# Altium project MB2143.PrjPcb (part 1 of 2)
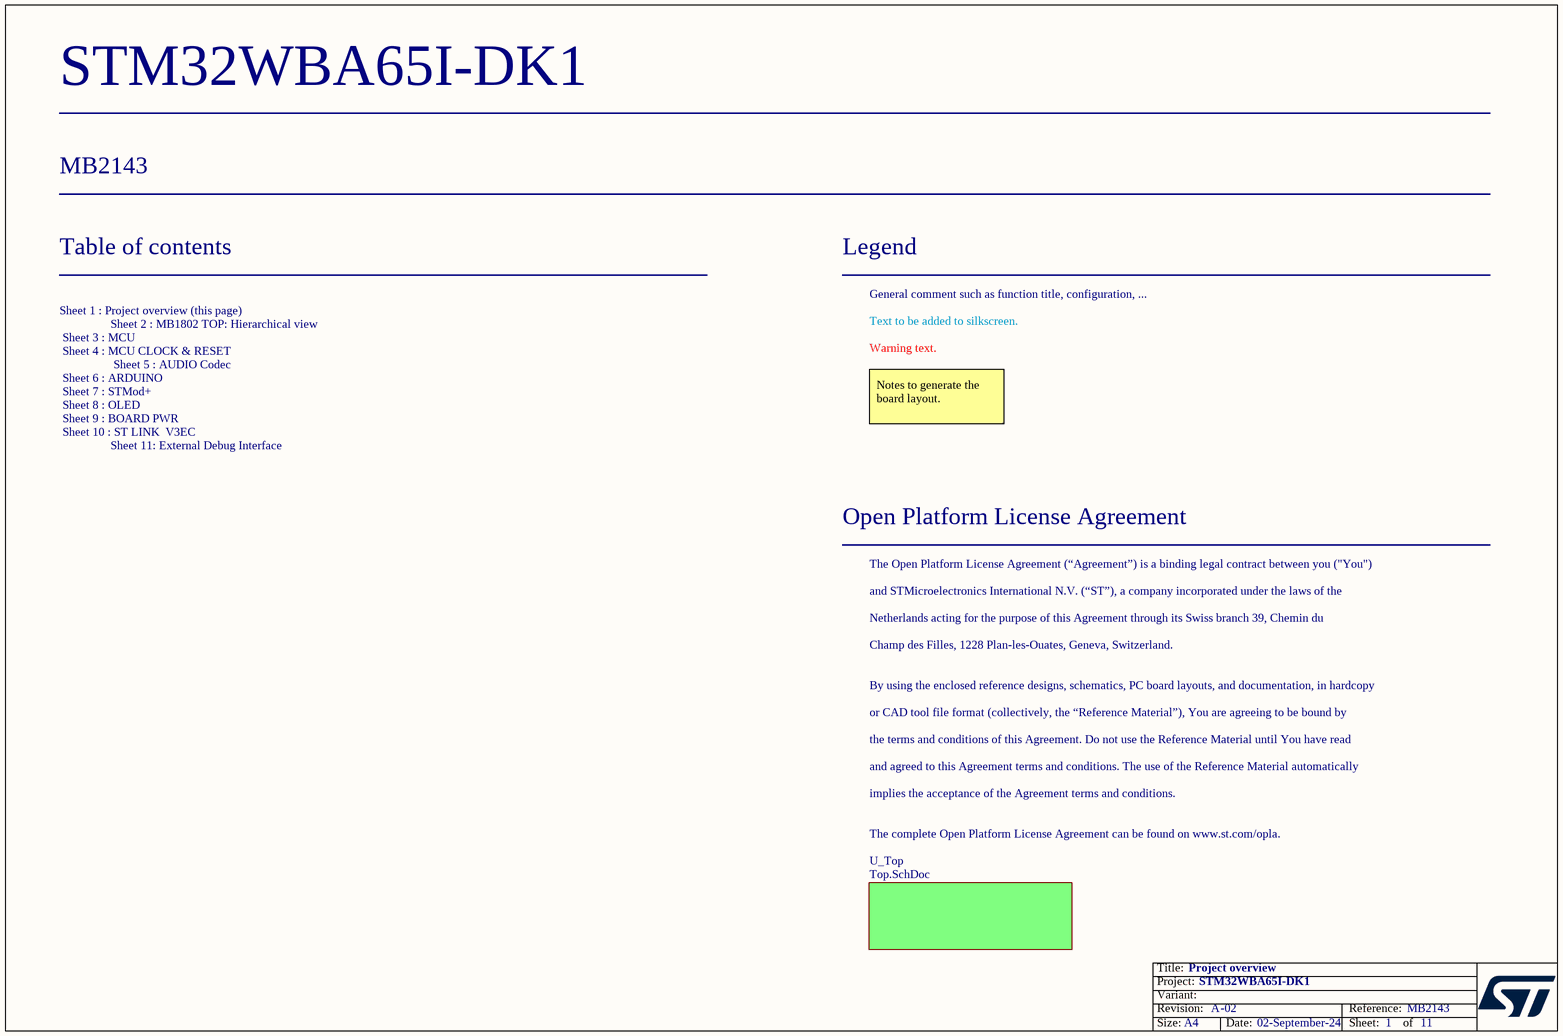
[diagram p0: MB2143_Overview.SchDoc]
Board_Assembly_Revision: 02; Board_Document_Date: 02-September-24; Board_Name: STM32WBA65I-DK1; Board_PCB_Revision: A; Board_Reference: MB2143
10 sheets, 267 parts. Net scope: flat (ports and power ports of the same name join across sheets).
Board file: MB2143.PcbDoc
Sheets:
  MB2143_Overview.SchDoc
    U_Top = Top.SchDoc
      U_Board_Power = Board_Power.SchDoc
      U_External_Debug_Interface = External_Debug_Interface.SchDoc
      U_OLED = OLED.SchDoc
      U_STLink_V3EC = STLink_V3EC.SchDoc
      U_MCU = MCU.SchDoc
      U_Arduino = Arduino.SchDoc
      U_USB_Joystick_Reset = USB_Joystick_Reset.SchDoc
      U_Audio_Codec = Audio_Codec.SchDoc

## Sheet MB2143_Overview.SchDoc: Project overview
size A4; Date: Not used; ApprovedBy: Not used; CheckedBy: Not used; Author: Not used; CompanyName: STMicroelectronics; DrawnBy: Not used; Engineer: Not used; Organization: Not used; Address1: Not used; Address2: Not used; Address3: Not used; Address4: Not used; DocumentNumber: 1; Revision: Not used; SheetNumber: 1; SheetTotal: 11

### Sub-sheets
U_Top = Top.SchDoc: no entries

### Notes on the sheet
- Table of contents
- Legend
- General comment such as function title, configuration, ...
- Text to be added to silkscreen.
- Warning text.
- Notes to generate the board layout.
- Open Platform License Agreement
- The Open Platform License Agreement (“Agreement”) is a binding legal contract between you ("You")
- and STMicroelectronics International N.V. (“ST”), a company incorporated under the laws of the
- Netherlands acting for the purpose of this Agreement through its Swiss branch 39, Chemin du
- Champ des Filles, 1228 Plan-les-Ouates, Geneva, Switzerland.
- Sheet 1 : Project overview (this page)
  Sheet 2 : MB1802 TOP: Hierarchical view
  Sheet 3 : MCU
  Sheet 4 : MCU CLOCK & RESET
  Sheet 5 : AUDIO Codec
  Sheet 6 : ARDUINO
  Sheet 7 : STMod+
  Sheet 8 : OLED
  Sheet 9 : BOARD PWR
  Sheet 10 : ST LINK  V3EC
  Sheet 11: External Debug Interface
- By using the enclosed reference designs, schematics, PC board layouts, and documentation, in hardcopy
- or CAD tool file format (collectively, the “Reference Material”), You are agreeing to be bound by
- the terms and conditions of this Agreement. Do not use the Reference Material until You have read
- and agreed to this Agreement terms and conditions. The use of the Reference Material automatically
- implies the acceptance of the Agreement terms and conditions.
- The complete Open Platform License Agreement can be found on www.st.com/opla.

## Sheet Top.SchDoc: Schematic sheet title to update
size A4; Date: Not used; ApprovedBy: Not used; CheckedBy: Not used; Author: Not used; CompanyName: STMicroelectronics; DrawnBy: Not used; Engineer: Not used; Organization: Not used; Address1: Not used; Address2: Not used; Address3: Not used; Address4: Not used; DocumentNumber: Not used; Revision: Not used; SheetNumber: 2; SheetTotal: 11
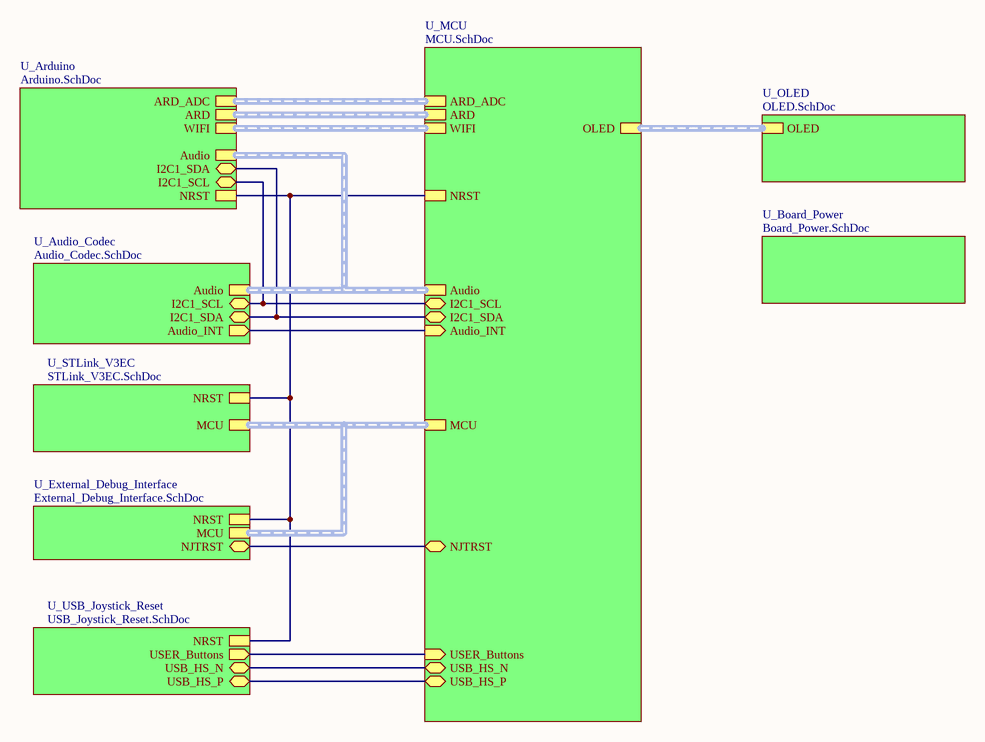
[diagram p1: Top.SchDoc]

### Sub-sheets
U_Arduino = Arduino.SchDoc: ARD (harness ARD), ARD_ADC (harness ARD_ADC), I2C1_SDA (bidir), I2C1_SCL (bidir), WIFI (harness WIFI), Audio (harness Audio), NRST
U_Audio_Codec = Audio_Codec.SchDoc: Audio (harness Audio), Audio_INT (out), I2C1_SDA (bidir), I2C1_SCL (bidir)
U_Board_Power = Board_Power.SchDoc: no entries
U_External_Debug_Interface = External_Debug_Interface.SchDoc: MCU (harness MCU), NJTRST (bidir), NRST
U_MCU = MCU.SchDoc: Audio (harness Audio), ARD_ADC (harness ARD_ADC), ARD (harness ARD), MCU (harness MCU), OLED (harness OLED), USER_Buttons (in), NJTRST (bidir), USB_HS_N (bidir), USB_HS_P (bidir), I2C1_SDA (bidir), I2C1_SCL (bidir), WIFI (harness WIFI), Audio_INT (in), NRST
U_OLED = OLED.SchDoc: OLED (harness OLED)
U_STLink_V3EC = STLink_V3EC.SchDoc: MCU (harness MCU), NRST
U_USB_Joystick_Reset = USB_Joystick_Reset.SchDoc: USER_Buttons (out), USB_HS_N (bidir), USB_HS_P (bidir), NRST

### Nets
(unnamed): sheet U_External_Debug_Interface/NJTRST, sheet U_MCU/NJTRST
(unnamed): sheet U_External_Debug_Interface/NRST, sheet U_STLink_V3EC/NRST, sheet U_MCU/NRST, sheet U_Arduino/NRST, sheet U_USB_Joystick_Reset/NRST  [a separate net that carries the same name]
(unnamed): sheet U_MCU/USER_Buttons, sheet U_USB_Joystick_Reset/USER_Buttons  [a separate net that carries the same name]
(unnamed): sheet U_MCU/USB_HS_N, sheet U_USB_Joystick_Reset/USB_HS_N  [a separate net that carries the same name]
(unnamed): sheet U_MCU/USB_HS_P, sheet U_USB_Joystick_Reset/USB_HS_P  [a separate net that carries the same name]
(unnamed): sheet U_MCU/I2C1_SDA, sheet U_Arduino/I2C1_SDA, sheet U_Audio_Codec/I2C1_SDA  [a separate net that carries the same name]
(unnamed): sheet U_MCU/I2C1_SCL, sheet U_Arduino/I2C1_SCL, sheet U_Audio_Codec/I2C1_SCL  [a separate net that carries the same name]
(unnamed): sheet U_MCU/Audio_INT, sheet U_Audio_Codec/Audio_INT  [a separate net that carries the same name]

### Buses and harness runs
harness sheet U_Arduino/ARD = sheet U_MCU/ARD
harness sheet U_Arduino/ARD_ADC = sheet U_MCU/ARD_ADC
harness sheet U_Arduino/Audio = sheet U_Audio_Codec/Audio = sheet U_MCU/Audio
harness sheet U_Arduino/WIFI = sheet U_MCU/WIFI
harness sheet U_External_Debug_Interface/MCU = sheet U_MCU/MCU = sheet U_STLink_V3EC/MCU
harness sheet U_MCU/OLED = sheet U_OLED/OLED

## Sheet Board_Power.SchDoc: Board_Power
size A4; Date: Not used; ApprovedBy: Not used; CheckedBy: Not used; Author: Not used; CompanyName: STMicroelectronics; DrawnBy: Not used; Engineer: Not used; Organization: Not used; Address1: Not used; Address2: Not used; Address3: Not used; Address4: Not used; DocumentNumber: Not used; Revision: Not used; SheetNumber: 9; SheetTotal: 11
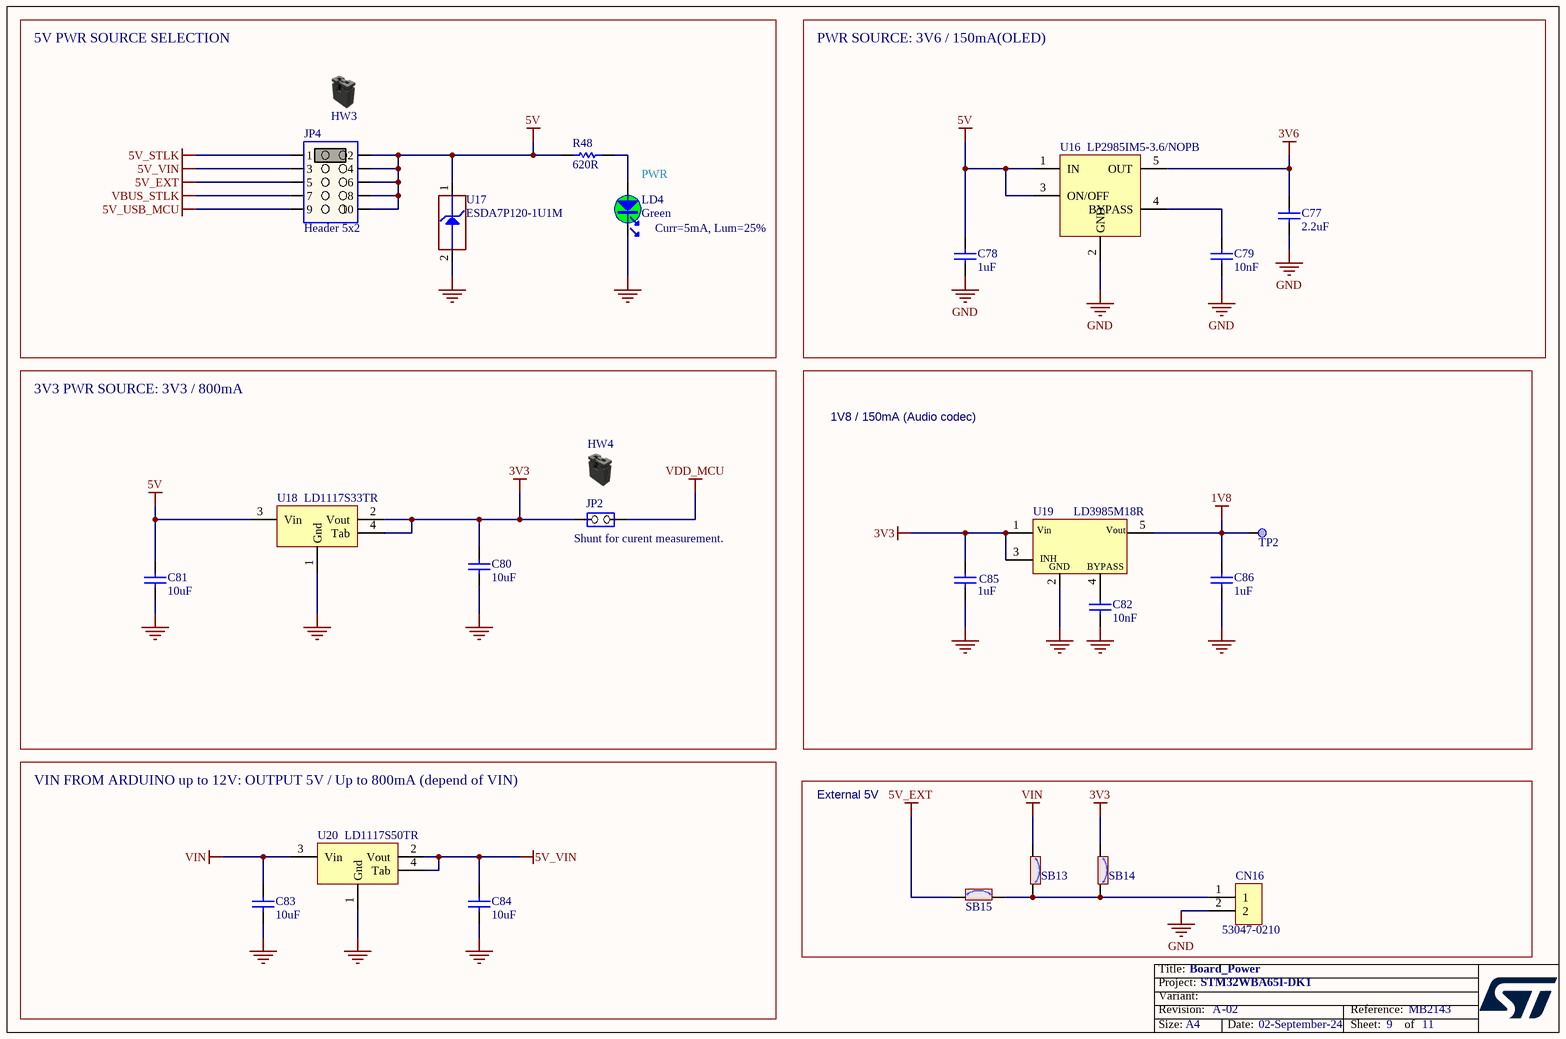
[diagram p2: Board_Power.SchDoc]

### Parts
C77  value 2.2uF  [C0603]  (hidden comment: Capacitor)
C78  value 1uF  [C0603]  (hidden comment: Capacitor)
C79  value 10nF  [C0402]  (hidden comment: Capacitor)
C80  value 10uF  [C0603]  (hidden comment: Capacitor)
C81  value 10uF  [C0603]  (hidden comment: Capacitor)
C82  value 10nF  [C0402]  (hidden comment: Capacitor)
C83  value 10uF  [C0603]  (hidden comment: Capacitor)
C84  value 10uF  [C0603]  (hidden comment: Capacitor)
C85  value 1uF  [C0402]  (hidden comment: Capacitor)
C86  value 1uF  [C0402]  (hidden comment: Capacitor)
CN16  Manufacturer_Part_Number: 53047-0210  [CON_MOLEX_53047-0210]  (hidden comment: Header 2x1)
HW3  (no value)  (mechanical)
HW4  Shunt Black 2.54mm  (value not drawn)  (mechanical)
JP2  value Shunt for curent measurement.  [CON_SAMTEC_TSW-102-07-G-S]  (hidden comment: Jumper_Header 2x1)
JP4  value Header 5x2  [CON_SAMTEC_TSW-105-07-X-D]  (hidden comment: Jumper_Header 5x2 Fitted 1-2)
LD4  value Green  [LED_0603_OSRAM_LG-Q396-PS-35_GREEN_1A2K_H0P4]  (hidden comment: LED_green)
R48  value 620R  [R0402]
SB13  (no value)  [SOLDER-BRIDGE_R0603-0R]
SB14  (no value)  [SOLDER-BRIDGE_R0603-0R]
SB15  (no value)  [SOLDER-BRIDGE_R0603-0R]
TP2  Test Point  [TP_SMD_0-3MM]  (value not drawn)  (no BOM)
U16  LP2985IM5-3.6/NOPB  [REG_SOT23-5L]
U17  value ESDA7P120-1U1M  [ESD_QFN1610_2N_1K_2A]  (hidden comment: ESD-TRANSIL)
U18  LD1117S33TR  [REG_SOT223-TAB]
U19  LD3985M18R  [REG_SOT23-5L]
U20  LD1117S50TR  [REG_SOT223-TAB]

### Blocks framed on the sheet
5V PWR SOURCE SELECTION: HW3 JP4 LD4 R48 U17
PWR SOURCE: 3V6 / 150mA(OLED): C77-C79 U16
3V3 PWR SOURCE: 3V3 / 800mA: C80 C81 HW4 JP2 U18
1V8 / 150mA (Audio codec): C82 C85 C86 TP2 U19
External 5V: CN16 SB13-SB15

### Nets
1V8: C86.2 TP2.1 U19.5(Vout)
3V3: C80.2 C85.2 JP2.2(NO) SB14.1 U18.2(Vout) U18.4(Tab) U19.1(Vin) U19.3(CE)
3V6: C77.1 U16.5(OUT)
5V: C78.1 C81.2 JP4.2 JP4.4 JP4.6 JP4.8 JP4.10 R48.2 U16.1(IN) U16.3(ON/OFF) U17.1(IO1) U18.3(Vin)
5V_EXT: JP4.5 SB15.1
5V_STLK: JP4.1
5V_USB_MCU: JP4.9
5V_VIN: C84.2 JP4.3 U20.2(Vout) U20.4(Tab)
GND: C77.2 C78.2 C79.2 C80.1 C81.1 C82.1 C83.1 C84.1 C85.1 C86.1 CN16.2 LD4.2 U16.2(GND) U17.2(GND) U18.1(Gnd) U19.2(GND) U20.1(Gnd)
VBUS_STLK: JP4.7
VDD_MCU: JP2.1(COMMON)  [project net VBAT]
VIN: C83.2 SB13.1 U20.3(Vin)
NetC79_1: C79.1 U16.4(BYPASS)
NetC82_2: C82.2 U19.4(BYPASS)
NetCN16_1: CN16.1 SB13.2 SB14.2 SB15.2
NetLD4_1: LD4.1 R48.1

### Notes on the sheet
- (near LD4) PWR
- (near LD4) Curr=5mA, Lum=25%
- VIN FROM ARDUINO up to 12V: OUTPUT 5V / Up to 800mA (depend of VIN)

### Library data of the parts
C77 = MCD-00654: Capacitor,2.2uF,16V, X5R,10%,0603,YAGEO; Manufacturer_Part_Number: CC0603KRX5R7BB225; Provided_By: SUBCO
C78 = MCD-00010: Capacitor, MLCC, 1uF, 16V, X5R, 10%, 0603, T=0,8mm; Manufacturer_Part_Number: CC0603KRX5R7BB105; Manufacturer: YAGEO; Provided_By: SUBCO; Initial_Board_Reference: MB1274; Item Type: Item; Path: ws/MCD_ApplicationBoards/Lists/MCDPARTSdatabase
C79 = MCD-00011: Capacitor, MLCC, 10nF, 16V, X7R, 10%, 0402, T=0.5mm; Manufacturer_Part_Number: CC0402KRX7R7BB103; Manufacturer: YAGEO; Provided_By: SUBCO
C80 C81 C83 C84 = MCD-00099: Capacitor, MLCC, 10uF, 10V, X5R, 10%, 0603, T=0,8mm; Manufacturer_Part_Number: GRM188R61A106KE69D; Manufacturer: MURATA; Provided_By: SUBCO; Initial_Board_Reference: MB1262; Item Type: Item; Path: ws/MCD_ApplicationBoards/Lists/MCDPARTSdatabase
C82 = MCD-00011: Capacitor, MLCC, 10nF, 16V, X7R, 10%, 0402, T=0.5mm; Manufacturer_Part_Number: CC0402KRX7R7BB103; Manufacturer: YAGEO; ECCN_US: EAR99; ECCN_EU: NEC; Provided_By: SUBCO
C85 C86 = MCD-01722: Capacitor, 1uF, 10V, X5R, 10%, 0402, T=0.5mm; Manufacturer_Part_Number: CC0402KRX5R6BB105; Manufacturer: YAGEO; Provided_By: SUBCO
CN16 = MCD-00655: Header, 2x1, 1.25mm, VR, TH, T=2.25mm/2.3mm; BMS_Part_Number: 9083002; Part_Type: Connector; Part_Preference: Recommended; Manufacturer: MOLEX; Order_Code_RS: 279-9213; Component_Country_Of_Origin: Unknown; ShowFields: YES; ID: 3091
HW3 = MCD-00043: SHUNT 2.54mm BLACK; Part_Type: Mechanical; Manufacturer_Part_Number: SNT-100-BK-G; Manufacturer: SAMTEC; Provided_By: Subcon; Initial_Board_Reference: MB1274
HW4 = MCD-00043: SHUNT 2.54mm BLACK; Manufacturer_Part_Number: SNT-100-BK-G; Manufacturer: SAMTEC; Part_Type: Mechanical; Provided_By: Subcon; Initial_Board_Reference: MB1274
JP2 = MCD-00045: Header, 2x1, 2,54mm, VR, TH, Height 5.84mm/2.54mm; Part_Type: Connector; Manufacturer_Part_Number: TSW-102-07-x-S; Manufacturer: SAMTEC; Provided_By: Subcon; Initial_Board_Reference: MB1274; Remark: 3D KO: BZ: 40098
JP4 = MCD-01203: Header, 5x2, 2.54mm, VR, TH, T=5.84mm/2.54mm; BMS_Part_Number: 9083523; Part_Type: Connector; Part_Preference: Recommended; Manufacturer: SAMTEC; Manufacturer_Part_Number: TSW-105-07-G-D; Full_Alternate_Internal_Part_Number: MCD-02391; Partial_Alternate_Internal_Part_Number: MCD-03596, MCD-03727, MCD-03840; Order_Code_RS: 161-2267; Component_Country_Of_Origin: China, Costa Rica, Malaysia, USA, Vietnam; Alternate_EMS: A; ShowFields: YES; ID: 3293
LD4 = MCD-02901: LED, Green, 2V, 20mA, 0603; Part_Type: Display; Part_Preference: Recommended; Manufacturer: EVERLIGHT; Manufacturer_Part_Number: 19-217/G7C-AN1P2/6T; Partial_Alternate_Internal_Part_Number: MCD-02400, MCD-00588; Component_Country_Of_Origin: China; ShowFields: YES; ID: 5017
R48 = MCD-00499: Resistor,620R,0402,1%,1/16W; Manufacturer_Part_Number: RC0402FR-07620RL; Manufacturer: YAGEO; Provided_By: Subcon
SB13-SB15 = MCD-00071: Solder Bridge ON; Part_Type: Mechanical; Provided_By: Subcon; Initial_Board_Reference: mb1274
TP2 = MCD-00630: Test Point 0.3mm; Part_Type: Mechanical
U16 = MCD-01030: LDO VOLTAGE REGULATOR, 3.6V, 150mA, 5-SOT-23, FULL REEL; Part_Type: IC; Manufacturer: TEXAS INSTRUMENTS; Provided_By: SUBCO
U17 = MCD-01026: High power transient voltage suppressor; Part_Type: Diode; Manufacturer: STMICROELECTRONICS; Provided_By: SUBCO with ST control; Initial_Board_Reference: MB1378; Remark: Footprint moved fromROU lib: DFN105P160X60-2N to global-lib: ESD_QFN1610_2N_1K_2A; Item Type: Item; Path: ws/MCD_ApplicationBoards/Lists/MCDPARTSdatabase
U18 = MCD-00089: LOW DROP FIXED AND ADJUSTABLE POSITIVE VOLTAGE REGULATORS (3.3 Volts); Part_Type: IC; Manufacturer: STMICROELECTRONICS; BMS_Part_Number: 9176186; Provided_By: SUBCO with ST control
U19 = MCD-00078: Ultra low drop-low noise BiCMOS voltage, regulators low ESR capacitors compatible; Part_Type: IC; Manufacturer: STMICROELECTRONICS; BMS_Part_Number: 9176159; ECCN_US: EAR99; ECCN_EU: NEC; Provided_By: SUBCO with ST control
U20 = MCD-00088: IC REG LDO 5V 0.8A SOT223; Manufacturer: STMICROELECTRONICS; ECCN_US: EAR99; ECCN_EU: NEC; Provided_By: Subcon; Initial_Board_Reference: MB1274

## Sheet External_Debug_Interface.SchDoc: External_Debug_Interface
size A4; Date: Not used; ApprovedBy: Not used; CheckedBy: Not used; Author: Not used; CompanyName: STMicroelectronics; DrawnBy: Not used; Engineer: Not used; Organization: Not used; Address1: Not used; Address2: Not used; Address3: Not used; Address4: Not used; DocumentNumber: Not used; Revision: Not used; SheetNumber: 11; SheetTotal: 11
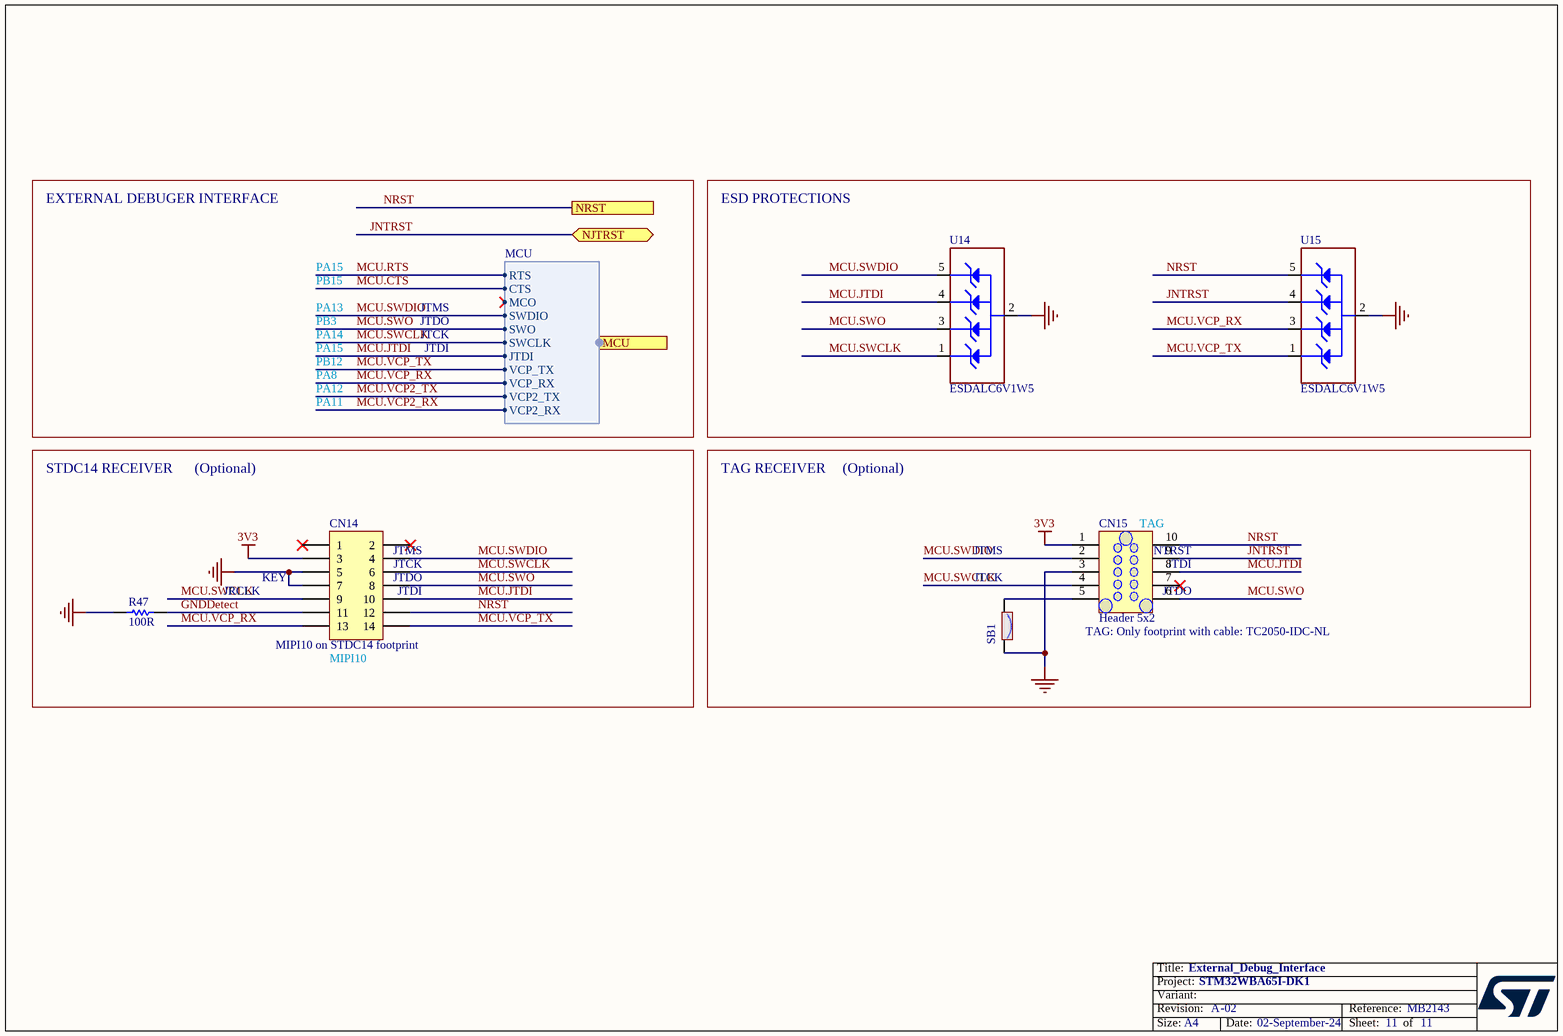
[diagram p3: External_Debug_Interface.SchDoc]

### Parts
CN14  value MIPI10 on STDC14 footprint  [CON_STDC14_Receiver_MEDIUM_WITH_MIPI10_3D]  (hidden comment: Header 7x2)
CN15  value Header 5x2  [CON_TAG-C_TC2050-IDC-NL]  (hidden comment: Tag-10-C)  (no BOM)
R47  value 100R  [R0402]  (hidden comment: Resistor)
SB1  (no value)  [SOLDER-BRIDGE_R0603-0R]
U14  ESDALC6V1W5  [ESD_SOT323-5L]
U15  ESDALC6V1W5  [ESD_SOT323-5L]

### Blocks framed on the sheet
ESD PROTECTIONS: U14 U15

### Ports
MCU (harness MCU), NJTRST (bidir), NRST

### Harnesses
MCU: MCO, SWDIO, SWO, VCP_TX, SWCLK, VCP_RX, JTDI, CTS, RTS, VCP2_RX, VCP2_TX

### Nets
3V3: CN14.3 CN15.1
GND: CN14.5 CN14.7 CN15.3 R47.1 SB1.2 U14.2(GND) U15.2(GND)
GNDDetect: CN14.11 R47.2
JNTRST: CN15.9 U15.4(IO3) ; port NJTRST
MCU.JTDI: CN14.10 CN15.8 U14.4(IO3) ; port MCU.JTDI
MCU.SWCLK: CN14.6 CN14.9 CN15.4 U14.1(IO1) ; port MCU.SWCLK
MCU.SWDIO: CN14.4 CN15.2 U14.5(IO4) ; port MCU.SWDIO
MCU.SWO: CN14.8 CN15.6 U14.3(IO2) ; port MCU.SWO
MCU.VCP_RX: CN14.13 U15.3(IO2) ; port MCU.VCP_RX
MCU.VCP_TX: CN14.14 U15.1(IO1) ; port MCU.VCP_TX
NRST: CN14.12 CN15.10 U15.5(IO4) ; port NRST
NetCN15_5: CN15.5 SB1.1

Not connected (* = marked no-connect by the designer): CN14 1* 2*; CN15 7*

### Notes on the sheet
- EXTERNAL DEBUGER INTERFACE
- PA15
- PB15
- PA13
- JTMS
- PB3
- PA14
- PA8
- PB12
- JTDO
- JTCK
- JTDI
- PA12
- PA11
- STDC14 RECEIVER
- (Optional)
- TAG RECEIVER
- (near CN14) KEY
- (near CN14) JTCK
- (near CN14) JTMS
- (near CN14) JTDO
- (near SB1) JTCK
- (near CN15) TAG
- (near CN15) JTDI
- (near CN15) JNTRST
- (near CN14) JRCLK
- (near CN14) JTDI
- (near CN15) TAG: Only footprint with cable: TC2050-IDC-NL
- (near CN15) JTDO
- (near CN14) MIPI10

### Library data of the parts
CN14 = MCD-01226: Header 5x2, 1.27mm, Dual row, Straight, Surface mount, vertical male connector. 3.05mm lead. Mates with FFSD connector. Footprint compatible with FTSH-107-01-L-DV,-K,-A,-P,-ES (STDC14 MEDIUM); Manufacturer_Part_Number: FTSH-105-01-L-DV-K; Manufacturer: SAMTEC; Provided_By: Subcon; Initial_Board_Reference: MCD16-052
CN15 = MCD-00031: Header_Plug-of-nails, 5x2, 1.27mm, No legs; Part_Type: Connector; Part_Preference: Recommended; ShowFields: YES; ID: 2486
R47 = MCD-00067: Resistor, 100R, 0402, +/- 1%, 1/16W; Part_Preference: Recommended; Manufacturer: YAGEO; Manufacturer_Part_Number: RC0402FR-07100RL; Component_Country_Of_Origin: China; ShowFields: YES; ID: 2527
SB1 = MCD-00071: as SB13 on sheet Board_Power
U14 U15 = MCD-00136: Dual Transil array for ESD protection; BMS_Part_Number: 9151112; Part_Type: Diode; Part_Preference: Recommended; Manufacturer: STMICROELECTRONICS; Manufacturer_HQ_COO: EU; Component_Country_Of_Origin: China

## Sheet OLED.SchDoc: OLED
size A4; Date: Not used; ApprovedBy: Not used; CheckedBy: Not used; Author: Not used; CompanyName: STMicroelectronics; DrawnBy: Not used; Engineer: Not used; Organization: Not used; Address1: Not used; Address2: Not used; Address3: Not used; Address4: Not used; DocumentNumber: Not used; Revision: Not used; SheetNumber: 8; SheetTotal: 11
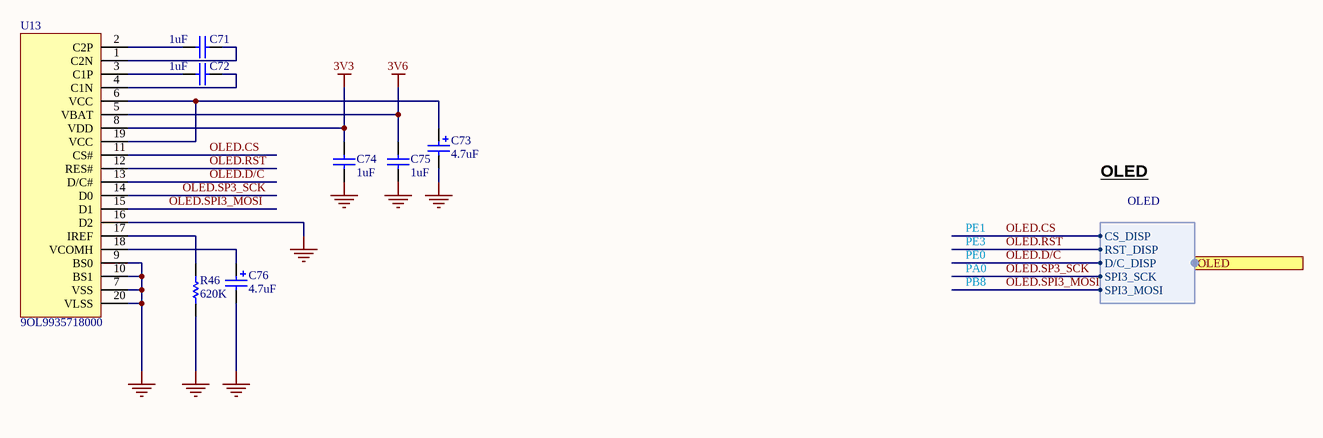
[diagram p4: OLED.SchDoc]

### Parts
C71  value 1uF  [C0603]
C72  value 1uF  [C0603]
C73  value 4.7uF  [CPOL_TAJ-A_1206_H180]  (hidden comment: ​Footprint CPOL_TAJ-A_1206_H180)
C74  value 1uF  [C0603]
C75  value 1uF  [C0603]
C76  value 4.7uF  [CPOL_TAJ-A_1206_H180]  (hidden comment: ​Footprint CPOL_TAJ-A_1206_H180)
R46  value 620K  [R0603]
U13  value 9OL9935718000  [OLED_RITDISPLAY_9OL9935718000]  (hidden comment: OLED_RITDISPLAY_9OL9935718000)

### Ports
OLED (harness OLED)

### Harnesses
OLED: CS_DISP, RST_DISP, D/C_DISP, SPI3_SCK, SPI3_MOSI

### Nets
3V3: C74.1 U13.8(VDD)
3V6: C75.1 U13.5(VBAT)
GND: C73.2 C74.2 C75.2 C76.2 R46.1 U13.7(VSS) U13.9(BS0) U13.10(BS1) U13.16(D2) U13.20(VLSS)
OLED.CS: U13.11(CS#) ; port OLED.CS_DISP
OLED.D/C: U13.13(D/C#) ; port OLED.D/C_DISP  [project net ARD.D2_IO]
OLED.RST: U13.12(RES#) ; port OLED.RST_DISP
OLED.SP3_SCK: U13.14(D0) ; port OLED.SPI3_SCK  [project net ARD_ADC.A5]
OLED.SPI3_MOSI: U13.15(D1) ; port OLED.SPI3_MOSI  [project net Mem_MOSI]
NetC71_1: C71.1 U13.2(C2P)
NetC71_2: C71.2 U13.1(C2N)
NetC72_1: C72.1 U13.3(C1P)
NetC72_2: C72.2 U13.4(C1N)
NetC73_1: C73.1 U13.6(VCC) U13.19(VCC)
NetC76_1: C76.1 U13.18(VCOMH)
NetR46_2: R46.2 U13.17(IREF)

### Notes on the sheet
- OLED
- PB8
- PA0
- PE1
- PE3
- PE0

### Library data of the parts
C71 C72 C74 C75 = MCD-00010: Capacitor, MLCC, 1uF, 16V, X5R, 10%, 0603, T=0,8mm; Manufacturer_Part_Number: CC0603KRX5R7BB105; Manufacturer: YAGEO; Provided_By: Subcon; Initial_Board_Reference: MB1274
C73 C76 = MCD-01043: Capacitor, Tantalum, 4.7µF, 25V, 10%, 1206; Manufacturer_Part_Number: 293D475X9025A2TE3; Manufacturer: VISHAY; Provided_By: Subcon; Initial_Board_Reference: MB1378
R46 = MCD-00506: Resistor,620K,0603,1%,1/10W; Manufacturer_Part_Number: RC0603FR-07620KL; Manufacturer: YAGEO; Provided_By: Subcon
U13 = MCD-01925: 128*64 Dots 20-pin OLED display; Part_Preference: Recommended; Component_Country_Of_Origin: Unknown; ShowFields: YES; ID: 4025

## Sheet STLink_V3EC.SchDoc: STLink_V3EC
size A3; Date: Not used; ApprovedBy: Not used; CheckedBy: Not used; Author: Not used; CompanyName: STMicroelectronics; DrawnBy: Not used; Engineer: Not used; Organization: Not used; Address1: Not used; Address2: Not used; Address3: Not used; Address4: Not used; DocumentNumber: Not used; Revision: Not used; SheetNumber: 10; SheetTotal: 11
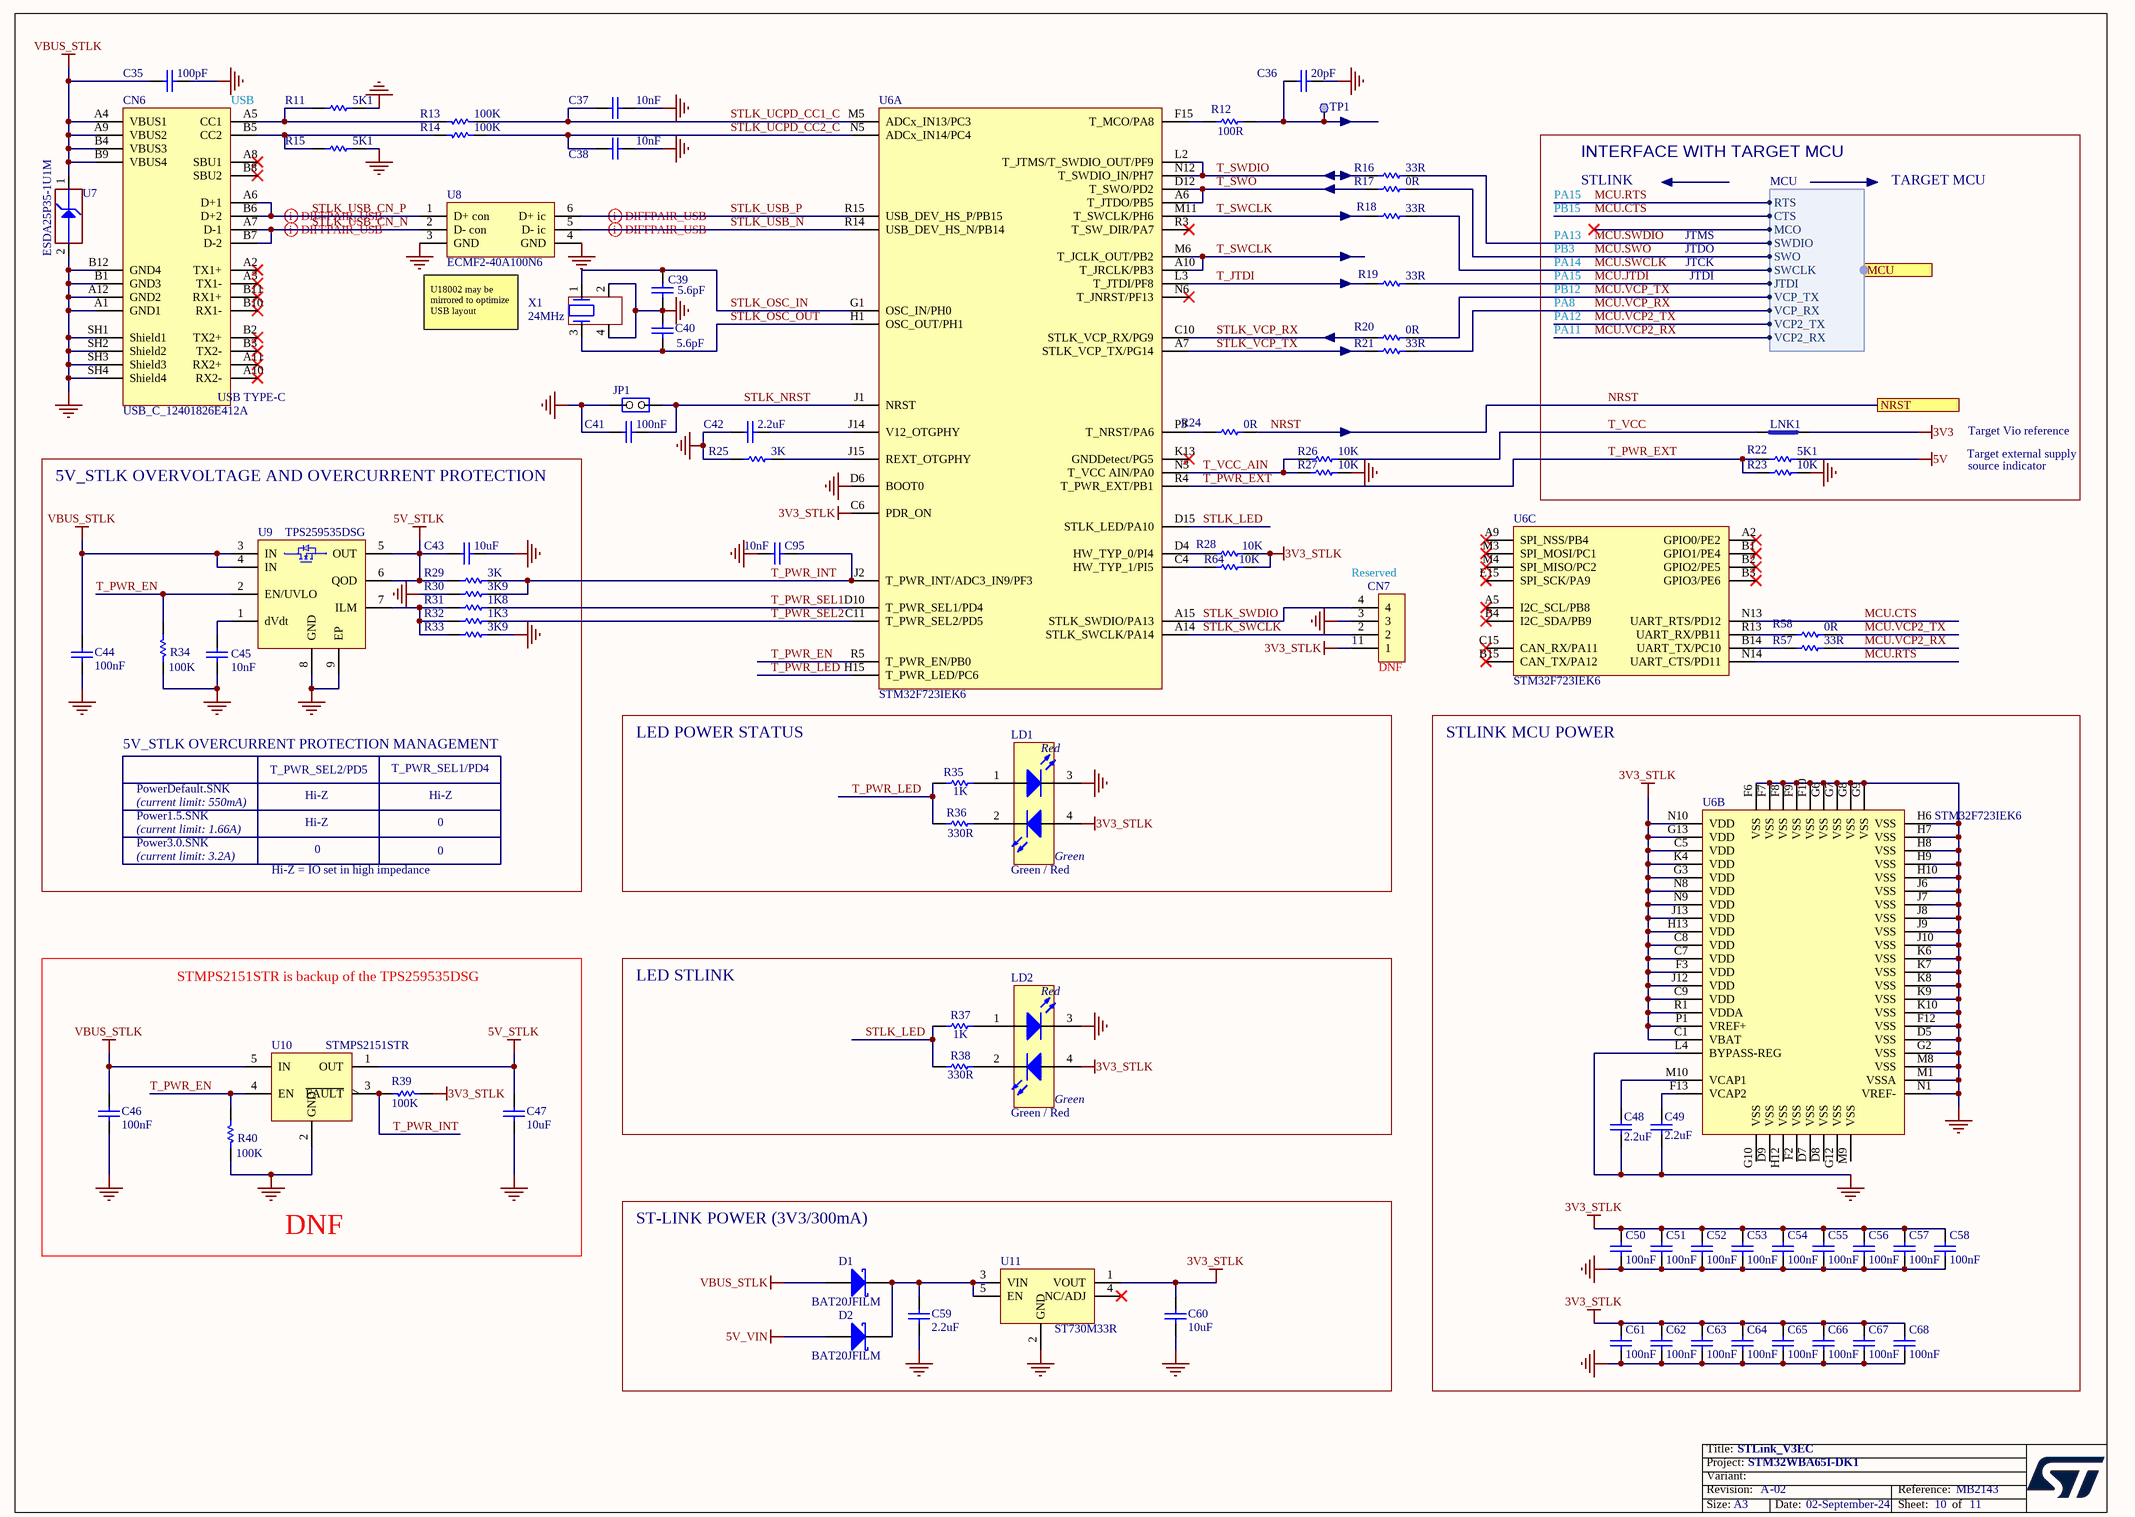
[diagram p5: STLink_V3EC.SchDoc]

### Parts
C35  value 100pF  [C0402]  (hidden comment: Capacitor)
C36  value 20pF  [C0402]  (hidden comment: Capacitor)
C37  value 10nF  [C0402]  (hidden comment: Capacitor)
C38  value 10nF  [C0402]  (hidden comment: Capacitor)
C39  value 5.6pF  [C0402]  (hidden comment: Capacitor)
C40  value 5.6pF  [C0402]  (hidden comment: Capacitor)
C41  value 100nF  [C0402]  (hidden comment: Capacitor)
C42  value 2.2uF  [C0402]  (hidden comment: Capacitor)
C43  value 10uF  [C0603]  (hidden comment: Capacitor)
C44  value 100nF  [C0402]  (hidden comment: Capacitor)
C45  value 10nF  [C0402]  (hidden comment: Capacitor)
C46  value 100nF  [C0402]  (hidden comment: Capacitor)
C47  value 10uF  [C0603]  (hidden comment: Capacitor)
C48  value 2.2uF  [C0402]  (hidden comment: Capacitor)
C49  value 2.2uF  [C0402]  (hidden comment: Capacitor)
C50  value 100nF  [C0402]  (hidden comment: Capacitor)
C51  value 100nF  [C0402]  (hidden comment: Capacitor)
C52  value 100nF  [C0402]  (hidden comment: Capacitor)
C53  value 100nF  [C0402]  (hidden comment: Capacitor)
C54  value 100nF  [C0402]  (hidden comment: Capacitor)
C55  value 100nF  [C0402]  (hidden comment: Capacitor)
C56  value 100nF  [C0402]  (hidden comment: Capacitor)
C57  value 100nF  [C0402]  (hidden comment: Capacitor)
C58  value 100nF  [C0402]  (hidden comment: Capacitor)
C59  value 2.2uF  [C0805]  (hidden comment: Capacitor)
C60  value 10uF  [C0603]  (hidden comment: Capacitor)
C61  value 100nF  [C0402]  (hidden comment: Capacitor)
C62  value 100nF  [C0402]  (hidden comment: Capacitor)
C63  value 100nF  [C0402]  (hidden comment: Capacitor)
C64  value 100nF  [C0402]  (hidden comment: Capacitor)
C65  value 100nF  [C0402]  (hidden comment: Capacitor)
C66  value 100nF  [C0402]  (hidden comment: Capacitor)
C67  value 100nF  [C0402]  (hidden comment: Capacitor)
C68  value 100nF  [C0402]  (hidden comment: Capacitor)
C95  value 10nF  [C0402]  (hidden comment: Capacitor)
CN6  value USB_C_12401826E412A  [CON_USB-TYPEC_AMPHENOL_12401826E412A]  (hidden comment: USB_TYPE_C_Receptacle)
CN7  Header 4x1  [CON_SAMTEC_TSW-104-07-G-S]  (value not drawn)
D1  value BAT20JFILM  [DIO_SOD323_1A_2K]  (hidden comment: SCHOTTKY_1A_2K)
D2  value BAT20JFILM  [DIO_SOD323_1A_2K]  (hidden comment: SCHOTTKY_1A_2K)
JP1  Jumper_Header 2x1  [CON_SAMTEC_TSW-102-07-G-S]  (value not drawn)
LD1  value Green / Red  [LED_BI-GR_WE-150141SV73110]  (hidden comment: LED_BICOLOR)
LD2  value Green / Red  [LED_BI-GR_WE-150141SV73110]  (hidden comment: LED_BICOLOR)
LNK1  link_200  [LINK200]  (value not drawn)  (no BOM)
R11  value 5K1  [R0402]  (hidden comment: Resistor)
R12  value 100R  [R0402]  (hidden comment: Resistor)
R13  value 100K  [R0402]  (hidden comment: Resistor)
R14  value 100K  [R0402]  (hidden comment: Resistor)
R15  value 5K1  [R0402]  (hidden comment: Resistor)
R16  value 33R  [R0402]  (hidden comment: Resistor)
R17  value 0R  [R0402]  (hidden comment: Resistor)
R18  value 33R  [R0402]  (hidden comment: Resistor)
R19  value 33R  [R0402]  (hidden comment: Resistor)
R20  value 0R  [R0402]  (hidden comment: Resistor)
R21  value 33R  [R0402]  (hidden comment: Resistor)
R22  value 5K1  [R0402]  (hidden comment: Resistor)
R23  value 10K  [R0402]  (hidden comment: Resistor)
R24  value 0R  [R0402]  (hidden comment: Resistor)
R25  value 3K  [R0402]  (hidden comment: Resistor)
R26  value 10K  [R0402]  (hidden comment: Resistor)
R27  value 10K  [R0402]  (hidden comment: Resistor)
R28  value 10K  [R0402]  (hidden comment: Resistor)
R29  value 3K  [R0402]  (hidden comment: Resistor)
R30  value 3K9  [R0402]  (hidden comment: Resistor)
R31  value 1K8  [R0402]  (hidden comment: Resistor)
R32  value 1K3  [R0402]  (hidden comment: Resistor)
R33  value 3K9  [R0402]  (hidden comment: Resistor)
R34  value 100K  [R0402]  (hidden comment: Resistor)
R35  value 1K  [R0402]  (hidden comment: Resistor)
R36  value 330R  [R0402]  (hidden comment: Resistor)
R37  value 1K  [R0402]  (hidden comment: Resistor)
R38  value 330R  [R0402]  (hidden comment: Resistor)
R39  value 100K  [R0402]  (hidden comment: Resistor)
R40  value 100K  [R0402]  (hidden comment: Resistor)
R57  value 33R  [R0402]  (hidden comment: Resistor)
R58  value 0R  [R0402]  (hidden comment: Resistor)
R64  value 10K  [R0402]  (hidden comment: Resistor)
TP1  Test Point  [TP_SMD_1MM]  (value not drawn)  (no BOM)
U6  value STM32F723IEK6  [ICC_UFBGA201_176+25_10X10_P065]  (hidden comment: STLINK-V3EC)  (parts A,B,C of 3)
U7  value ESDA25P35-1U1M  [ESD_QFN1610_2N_1K_2A]  (hidden comment: ESD-TRANSIL)
U8  ECMF2-40A100N6  [ESD_UQFN-6L_1P45X1P4_P040]
U9  TPS259535DSG  [ICC_WSON8-EPAD_2X2_P050]
U10  STMPS2151STR  [MOS_SOT23-5L]
U11  ST730M33R  [ICC_SOT23-5L_H1P45]
X1  value 24MHz  [CRY_NX2016SA_4P]  (hidden comment: XTAL_4_PINS)

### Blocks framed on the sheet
INTERFACE WITH TARGET MCU: LNK1 R22 R23
5V_STLK OVERVOLTAGE AND OVERCURRENT PROTECTION: C43-C45 R29-R34 U9
LED POWER STATUS: LD1 R35 R36
STLINK MCU POWER: C48-C58 C61-C68 U6
DNF: C46 C47 R39 R40 U10
LED STLINK: LD2 R37 R38
ST-LINK POWER (3V3/300mA): C59 C60 D1 D2 U11

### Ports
MCU (harness MCU), NRST

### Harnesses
MCU: MCO, SWDIO, SWO, VCP_TX, SWCLK, VCP_RX, JTDI, CTS, RTS, VCP2_RX, VCP2_TX

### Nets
3V3: LNK1.1
3V3_STLK: C50.1 C51.1 C52.1 C53.1 C54.1 C55.1 C56.1 C57.1 C58.1 C60.2 C61.1 C62.1 C63.1 C64.1 C65.1 C66.1 C67.1 C68.1 CN7.1 LD1.4(Green_anode) LD2.4(Green_anode) R28.2 R39.1 R64.2 U6.C1(VBAT) U6.C5(VDD) U6.C6(PDR_ON) U6.C7(VDD) U6.C8(VDD) U6.C9(VDD) U6.F3(VDD) U6.G3(VDD) U6.G13(VDD) U6.H13(VDD) U6.J12(VDD) U6.J13(VDD) U6.K4(VDD) U6.N8(VDD) U6.N9(VDD) U6.N10(VDD) U6.P1(VREF+) U6.R1(VDDA) U11.1(VOUT)
5V: R22.2
5V_STLK: C43.2 C47.2 R29.1 U9.5(OUT) U9.6(QOD) U10.1(OUT)
5V_VIN: D2.1(A)
GND: C35.2 C36.1 C37.2 C38.2 C39.1 C40.2 C41.1 C42.1 C43.1 C44.1 C45.1 C46.1 C47.1 C48.1 C49.1 C50.2 C51.2 C52.2 C53.2 C54.2 C55.2 C56.2 C57.2 C58.2 C59.1 C60.1 C61.2 C62.2 C63.2 C64.2 C65.2 C66.2 C67.2 C68.2 C95.2 CN6.A1(GND1) CN6.A12(GND2) CN6.B1(GND3) CN6.B12(GND4) CN6.SH1(Shield1) CN6.SH2(Shield2) CN6.SH3(Shield3) CN6.SH4(Shield4) CN7.3 JP1.2(NO) LD1.3(RED_cathode) LD2.3(RED_cathode) R11.2 R15.2 R23.2 R25.2 R27.2 R30.1 R33.2 R34.1 R40.1 U6.D5(VSS) U6.D6(BOOT0) U6.F6(VSS) U6.F7(VSS) U6.F8(VSS) U6.F9(VSS) U6.F10(VSS) U6.F12(VSS) U6.G2(VSS) U6.G6(VSS) U6.G7(VSS) U6.G8(VSS) U6.G9(VSS) U6.H6(VSS) U6.H7(VSS) U6.H8(VSS) U6.H9(VSS) U6.H10(VSS) U6.J6(VSS) U6.J7(VSS) U6.J8(VSS) U6.J9(VSS) U6.J10(VSS) U6.K6(VSS) U6.K7(VSS) U6.K8(VSS) U6.K9(VSS) U6.K10(VSS) U6.L4(BYPASS-REG) U6.M1(VSSA) U6.M8(VSS) U6.N1(VREF-) U7.2(GND) U8.3(GND) U8.4(GND) U9.8(GND) U9.9(EP) U10.2(GND) U11.2(GND) X1.2 X1.4
VBUS_STLK: C35.1 C44.2 C46.2 CN6.A4(VBUS1) CN6.A9(VBUS2) CN6.B4(VBUS3) CN6.B9(VBUS4) D1.1(A) U7.1(IO1) U9.3(IN) U9.4(IN) U10.5(IN)
MCU.CTS: U6.N13(UART_RTS/PD12) ; port MCU.CTS
MCU.JTDI: R19.2 ; port MCU.JTDI
MCU.RTS: U6.N14(UART_CTS/PD11) ; port MCU.RTS
MCU.SWCLK: R18.2 ; port MCU.SWCLK
MCU.SWDIO: R16.2 ; port MCU.SWDIO
MCU.SWO: R17.2 ; port MCU.SWO
MCU.VCP2_RX: R57.2 ; port MCU.VCP2_RX
MCU.VCP2_TX: R58.2 ; port MCU.VCP2_TX
MCU.VCP_RX: R21.2 ; port MCU.VCP_RX
MCU.VCP_TX: R20.2 ; port MCU.VCP_TX
NRST: R24.2 ; port NRST
STLK_LED: R37.2 R38.1 U6.D15(STLK_LED/PA10)
STLK_NRST: C41.2 JP1.1(COMMON) U6.J1(NRST)
STLK_OSC_IN: C39.2 U6.G1(OSC_IN/PH0) X1.1
STLK_OSC_OUT: C40.1 U6.H1(OSC_OUT/PH1) X1.3
STLK_SWCLK: CN7.2 U6.A14(STLK_SWCLK/PA14)
STLK_SWDIO: CN7.4 U6.A15(STLK_SWDIO/PA13)
STLK_UCPD_CC1_C: C37.1 R13.1 U6.M5(ADCx_IN13/PC3)
STLK_UCPD_CC2_C: C38.1 R14.1 U6.N5(ADCx_IN14/PC4)
STLK_USB_CN_N: CN6.A7(D-1) CN6.B7(D-2) U8.2(D-_con)
STLK_USB_CN_P: CN6.A6(D+1) CN6.B6(D+2) U8.1(D+_con)
STLK_USB_N: U6.R14(USB_DEV_HS_N/PB14) U8.5(D-_ic)
STLK_USB_P: U6.R15(USB_DEV_HS_P/PB15) U8.6(D+_ic)
STLK_VCP_RX: R20.1 U6.C10(STLK_VCP_RX/PG9)
STLK_VCP_TX: R21.1 U6.A7(STLK_VCP_TX/PG14)
T_JTDI: R19.1 U6.L3(T_JTDI/PF8)
T_PWR_EN: R34.2 R40.2 U6.R5(T_PWR_EN/PB0) U9.2(EN/UVLO) U10.4(EN)
T_PWR_EXT: R22.1 R23.1 U6.R4(T_PWR_EXT/PB1)
T_PWR_INT: C95.1 R29.2 R30.2 R39.2 U6.J2(T_PWR_INT/ADC3_IN9/PF3) U10.3(~{FAULT})
T_PWR_LED: R35.2 R36.2 U6.H15(T_PWR_LED/PC6)
T_PWR_SEL1: R31.2 U6.D10(T_PWR_SEL1/PD4)
T_PWR_SEL2: R32.2 U6.C11(T_PWR_SEL2/PD5)
T_SWCLK: R18.1 U6.A10(T_JRCLK/PB3) U6.M6(T_JCLK_OUT/PB2) U6.M11(T_SWCLK/PH6)
T_SWDIO: R16.1 U6.L2(T_JTMS/T_SWDIO_OUT/PF9) U6.N12(T_SWDIO_IN/PH7)
T_SWO: R17.1 U6.A6(T_JTDO/PB5) U6.D12(T_SWO/PD2)
T_VCC: LNK1.2 R26.2
T_VCC_AIN: R26.1 R27.1 U6.N3(T_VCC_AIN/PA0)
NetC36_2: C36.2 R12.2 TP1.1
NetC42_2: C42.2 U6.J14(V12_OTGPHY)
NetC45_2: C45.2 U9.1(dVdt)
NetC48_2: C48.2 U6.M10(VCAP1)
NetC49_2: C49.2 U6.F13(VCAP2)
NetC59_2: C59.2 D1.2(K) D2.2(K) U11.3(VIN) U11.5(EN)
NetCN6_A5: CN6.A5(CC1) R11.1 R13.2
NetCN6_B5: CN6.B5(CC2) R14.2 R15.1
NetLD1_1: LD1.1(Red_anode) R35.1
NetLD1_2: LD1.2(Green_cathode) R36.1
NetLD2_1: LD2.1(Red_anode) R37.1
NetLD2_2: LD2.2(Green_cathode) R38.2
NetR12_1: R12.1 U6.F15(T_MCO/PA8)
NetR24_1: R24.1 U6.P3(T_NRST/PA6)
NetR25_1: R25.1 U6.J15(REXT_OTGPHY)
NetR28_1: R28.1 U6.D4(HW_TYP_0/PI4)
NetR31_1: R31.1 R32.1 R33.1 U9.7(ILM)
NetR57_1: R57.1 U6.B14(UART_TX/PC10)
NetR58_1: R58.1 U6.R13(UART_RX/PB11)
NetR64_1: R64.1 U6.C4(HW_TYP_1/PI5)

Not connected (* = marked no-connect by the designer): CN6 A2(TX1+)* A3(TX1-)* A8(SBU1)* A10(RX2-)* A11(RX2+)* B2(TX2+)* B3(TX2-)* B8(SBU2)* B10(RX1-)* B11(RX1+)*; U6 A2(GPIO0/PE2)* A5(I2C_SCL/PB8)* A9(SPI_NSS/PB4)* B1(GPIO1/PE4)* B2(GPIO2/PE5)* B3(GPIO3/PE6)* B4(I2C_SDA/PB9)* B15(CAN_TX/PA12)* C15(CAN_RX/PA11)* D7(VSS) D8(VSS) D9(VSS) E15(SPI_SCK/PA9)* F2(VSS) G10(VSS) G12(VSS) H12(VSS) K13(GNDDetect/PG5)* M3(SPI_MOSI/PC1)* M4(SPI_MISO/PC2)* M9(VSS) N6(T_JNRST/PF13)* R3(T_SW_DIR/PA7)*; U11 4(NC/ADJ)*

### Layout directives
differential pair; rule ? : STLK_USB_CN_N, STLK_USB_CN_P, STLK_USB_N, STLK_USB_P

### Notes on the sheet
- (near CN6) USB
- STLINK
- TARGET MCU
- PA15
- PB15
- PB3
- PA13
- JTMS
- JTDO
- (near U8) U18002 may be mirrored to optimize USB layout
- PA14
- PA8
- PB12
- PA12
- JTCK
- JTDI
- PA11
- Target external supply
- Target Vio reference
- source indicator
- (near CN7) Reserved
- (near CN7) 1
- (near CN7) DNF
- 5V_STLK OVERCURRENT PROTECTION MANAGEMENT
- PowerDefault.SNK
- T_PWR_SEL2/PD5
- T_PWR_SEL1/PD4
- (current limit: 550mA)
- (current limit: 1.66A)
- (current limit: 3.2A)
- Power1.5.SNK
- Power3.0.SNK
- Hi-Z
- 0
- Hi-Z = IO set in high impedance
- STMPS2151STR is backup of the TPS259535DSG

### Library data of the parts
C35 = MCD-00205: Capacitor, MLCC, 100pF, 50V, NPO, +/-5%, 0402, T=0.5mm; Part_Preference: Recommended; Manufacturer: YAGEO; Manufacturer_Part_Number: CC0402JRNPO9BN101; Component_Country_Of_Origin: China; ShowFields: YES; ID: 2658
C36 = MCD-00016: Capacitor, MLCC, 20pF, 50V, NPO, +/- 5%, 0402, T=0.5mm; Manufacturer_Part_Number: CC0402JRNPO9BN200; Manufacturer: YAGEO; Part_Preference: Recommended; Component_Country_Of_Origin: China; ShowFields: YES; ID: 2479
C37 C38 C45 C95 = MCD-02198: Capacitor, MLCC, 10nF, 50V, X7R, +/-10%, 0402, T=0.5mm; Part_Preference: Recommended; Manufacturer: YAGEO; Manufacturer_Part_Number: CC0402KRX7R9BB103; Order_Code_RS: 6169644; Component_Country_Of_Origin: China; ShowFields: YES; ID: 4298
C39 C40 = MCD-01374: Capacitor, MLCC, 5.6pF, 50V, NPO, +/-0.1pF, 0402, T=0.5mm; Part_Preference: Recommended; Manufacturer: YAGEO; Manufacturer_Part_Number: CC0402BRNPO9BN5R6; Component_Country_Of_Origin: China; ShowFields: YES; ID: 3474
C41 C50-C58 C61-C68 = MCD-00006: Capacitor, MLCC, 100nF, 16V, X7R, +/-10%, 0402, T=0.5mm; Manufacturer_Part_Number: CC0402KRX7R7BB104; Manufacturer: YAGEO; Part_Preference: Recommended; Order_Code_RS: 616-9701; Component_Country_Of_Origin: China; ShowFields: YES; ID: 2474
C42 C48 C49 = MCD-02606: Capacitor, MLCC, 2.2uF, 6.3V, X5R, +/-10%, 0402, T=0.5mm; Part_Preference: Recommended; Manufacturer: YAGEO; Manufacturer_Part_Number: CC0402KRX5R5BB225; Order_Code_RS: 1992205; ShowFields: YES; ID: 4712
C43 C60 = MCD-00099: Capacitor, MLCC, 10uF, 10V, X5R, +/-10%, 0603, T=0.8mm; Part_Preference: Recommended; Manufacturer: MURATA; Manufacturer_Part_Number: GRM188R61A106KE69D; Order_Code_RS: 170-6168; Component_Country_Of_Origin: Japan; ShowFields: YES; ID: 2770
C44 C46 = MCD-02355: Capacitor, MLCC, 100nF, 25V, X7R, +/-10%, 0402, T=0.5mm; Part_Preference: Recommended; Manufacturer: WALSIN; Manufacturer_Part_Number: 0402B104K250CT; Order_Code_RS: 176-3114; Component_Country_Of_Origin: Unknown; ShowFields: YES; ID: 4461
C47 = MCD-00099: Capacitor, MLCC, 10uF, 10V, X5R, +/-10%, 0603, T=0.8mm; Part_Preference: Recommended; Manufacturer: MURATA; Manufacturer_Part_Number: GRM188R61A106KE69D; Order_Code_RS: 170-6168; Component_Country_Of_Origin: Japan
C59 = MCD-02372: Capacitor, MLCC, 2.2uF, 25V, X7R, +/-10%, 0805, T=1,25mm; Manufacturer_Part_Number: GRM21BR71E225KE11L; Manufacturer: MURATA; Part_Preference: Recommended; Component_Country_Of_Origin: Japan; ShowFields: YES; ID: 4478
CN6 = MCD-03232: USB_TypeC, 24 pins, RA, SMD, T=2.96mm; Part_Type: Connector; Part_Preference: Recommended; Manufacturer: AMPHENOL ICC; Manufacturer_Part_Number: 12401826E412A; Component_Country_Of_Origin: China°; ShowFields: YES; ID: 5348
CN7 = MCD-00029: Header, 4x1, 2.54mm, VR, TH, T=5.84mm/2.54mm; Manufacturer_Part_Number: TSW-104-07-G-S; Manufacturer: SAMTEC; Part_Type: Connector; Part_Preference: Recommended; Order_Code_RS: 161-2261; Component_Country_Of_Origin: China, Costa Rica, Malaysia, United States, Vietnam; ShowFields: YES; ID: 2487
D1 D2 = MCD-03011: Signal Schottky Diode, If=1A, Ifsm=5A, Vf =0.54V@1A, Vrrm=23V, Ir = 0.65µA@5V, SOD-323; Part_Preference: Recommended; Manufacturer: STMICROELECTRONICS; Order_Code_RS: 165-7545; ShowFields: YES; ID: 5127
JP1 = MCD-00045: Header, 2x1, 2.54mm, VR, TH, T=5.84mm/2.54mm; Part_Preference: Recommended; Part_Type: Connector; Manufacturer: SAMTEC; Manufacturer_Part_Number: TSW-102-07-G-S; Alternate_Internal_Part_Number: MCD-02390; Order_Code_RS: 155-5312; Component_Country_Of_Origin: China, Costa Rica, Malaysia, United States, Vietnam; ShowFields: YES; ID: 2545
LD1 LD2 = MCD-02631: LED Bicolor, Green/Red, 2V, 20mA,  4-PLCC; Part_Type: Display; Part_Preference: Recommended; Manufacturer: WURTH ELEKTRONIK; Manufacturer_Part_Number: 150141SV73110; Order_Code_RS: 184-6963; Component_Country_Of_Origin: China; ShowFields: YES; ID: 4737
LNK1 = MCD-02777: Track link on PCB 200um width for layout routing. No component assembly and no component in BOM; Part_Type: Misc; Part_Preference: Recommended; Manufacturer: STM; ShowFields: YES; ID: 4889
R11 R15 R22 = MCD-00333: Resistor, 5K1, 0402, +/-1%, 1/16W; Part_Preference: Recommended; Manufacturer: YAGEO; Manufacturer_Part_Number: RC0402FR-075K1L; Component_Country_Of_Origin: China; ShowFields: YES; ID: 2944
R12 = MCD-00067: as R47 on sheet External_Debug_Interface
R13 R14 R34 R39 R40 = MCD-00059: Resistor, 100K, 0402, +/-1%, 1/16W; Manufacturer_Part_Number: RC0402FR-07100KL; Manufacturer: YAGEO; Part_Preference: Recommended; Component_Country_Of_Origin: China; ShowFields: YES; ID: 2533
R16 R18 R19 R21 R57 = MCD-00455: Resistor, 33R, 0402, +/-1%, 1/16W; Part_Preference: Recommended; Manufacturer: YAGEO; Manufacturer_Part_Number: RC0402FR-0733RL; Component_Country_Of_Origin: China; ShowFields: YES; ID: 2821
R17 R20 R24 R58 = MCD-00052: Resistor, 0R, 0402, +/-5%, 1/16W; Part_Preference: Recommended; Manufacturer: YAGEO; Manufacturer_Part_Number: RC0402JR-070RL; Order_Code_RS: 618-5804; Component_Country_Of_Origin: China; ShowFields: YES; ID: 2540
R23 R26-R28 R64 = MCD-00053: Resistor, 10K, 0402, +/-1%, 1/16W; Manufacturer_Part_Number: RC0402FR-0710KL; Manufacturer: YAGEO; BMS_Part_Number: 9131590; Part_Preference: Recommended; Component_Country_Of_Origin: China; ShowFields: YES; ID: 2539
R25 = MCD-00185: Resistor, 3K, 0402, +/-1%, 1/16W; Manufacturer_Part_Number: RC0402FR-073KL; Manufacturer: YAGEO; Part_Preference: Recommended; Component_Country_Of_Origin: China; ShowFields: YES; ID: 2682
R29 = MCD-00185: Resistor, 3K, 0402, +/-1%, 1/16W; Part_Preference: Recommended; Manufacturer: YAGEO; Manufacturer_Part_Number: RC0402FR-073KL; Component_Country_Of_Origin: China; ShowFields: YES; ID: 2682
R30 R33 = MCD-02455: Resistor, 3K9, 0402, +/-1%, 1/16W, +/-100ppm/°C; Part_Preference: Recommended; Manufacturer: YAGEO; Manufacturer_Part_Number: RC0402FR-073K9L; Order_Code_RS: 198-7783; Component_Country_Of_Origin: China; ShowFields: YES; ID: 4561
R31 = MCD-00409: Resistor, 1K8, 0402, +/-1%, 1/16W; Part_Preference: Recommended; Manufacturer: YAGEO; Manufacturer_Part_Number: RC0402FR-071K8L; Component_Country_Of_Origin: China; ShowFields: YES; ID: 2871
R32 = MCD-00381: Resistor, 1K3, 0402, +/-1%, 1/16W; Part_Preference: Recommended; Manufacturer: YAGEO; Manufacturer_Part_Number: RC0402FR-071K3L; Component_Country_Of_Origin: China; ShowFields: YES; ID: 2898
R35 R37 = MCD-02665: Resistor, 1K, 0402, +/-0.1%, 1/16W, +/-25ppm/°C; Part_Preference: Recommended; Manufacturer: YAGEO; Manufacturer_Part_Number: RT0402BRD071KL; Order_Code_RS: 199-1298; ShowFields: YES; ID: 4771
R36 R38 = MCD-00062: Resistor, 330R, 0402, +/-1%, 1/16W; Part_Preference: Recommended; Manufacturer: YAGEO; Manufacturer_Part_Number: RC0402FR-07330RL; Component_Country_Of_Origin: China; ShowFields: YES; ID: 2529
TP1 = MCD-00074: Test Point 1mm; Part_Type: Misc; Part_Preference: Recommended; ShowFields: YES; ID: 2518
U6 = MCD-03851: MCU, ARM Cortex-M7 32-bit, 512KB Flash, 276KB RAM, With Crypto; Part_Type: IC; Part_Preference: Recommended; Manufacturer: STMICROELECTRONICS; Component_Country_Of_Origin: Philippines; ShowFields: YES; ID: 5967
U7 = MCD-01207: High power Transient voltage suppressor:25V/35A EOS and ESD transients protection.; Part_Type: Diode; Manufacturer: STMICROELECTRONICS; BMS_Part_Number: 9179045; Part_Preference: Recommended; Manufacturer_HQ_COO: EU; Component_Country_Of_Origin: China; ShowFields: YES; ID: 3289
U8 = MCD-03060: IC, ESD protection and Common Filter High Speed serial Interfaces, 10.7 GHz; Part_Preference: Recommended; Manufacturer: STMICROELECTRONICS; Component_Country_Of_Origin: China; ShowFields: YES; ID: 5176
U9 = MCD-02532: IC, eFuse with Fast Overvoltage Protection 2.7V to 18V 4A 34mOhm 8-Pin WSON; Part_Preference: Recommended; Manufacturer: TEXAS INSTRUMENTS; ShowFields: YES; ID: 4638
U10 = MCD-00159: 500mA, Enhanced single channel power switches with active high enable pin; Part_Type: IC; Manufacturer: STMICROELECTRONICS; Alternate_Manufacturer_Part_Number: TPS2051C; Alternate_Manufacturer: TEXAS INSTRUMENTS; BMS_Part_Number: 9159009; Provided_By: Subcon; Initial_Board_Reference: MB1264
U11 = MCD-02514: LDO, 3.3V, 300mA, High input voltage: 2.5V to 28V, SOT23-5L; Part_Type: IC; Part_Preference: Recommended; Manufacturer: STMICROELECTRONICS; Component_Country_Of_Origin: Malaysia; ShowFields: YES; ID: 4620
X1 = MCD-01036: Crystal, 24MHz, 6pF, +/-20ppm, 80R, 2x1.6mm; BMS_Part_Number: 9157045; Part_Type: Crystal_Osc; Part_Preference: Recommended; Manufacturer: NDK; Manufacturer_Part_Number: NX2016SA-24MHZ-EXS00A-CS10820; Component_Country_Of_Origin: Unknown

## Sheet MCU.SchDoc: MCU
size A3; Date: Not used; ApprovedBy: Not used; CheckedBy: Not used; Author: Not used; CompanyName: STMicroelectronics; DrawnBy: Not used; Engineer: Not used; Organization: Not used; Address1: Not used; Address2: Not used; Address3: Not used; Address4: Not used; DocumentNumber: Not used; Revision: Not used; SheetNumber: 3; SheetTotal: 11
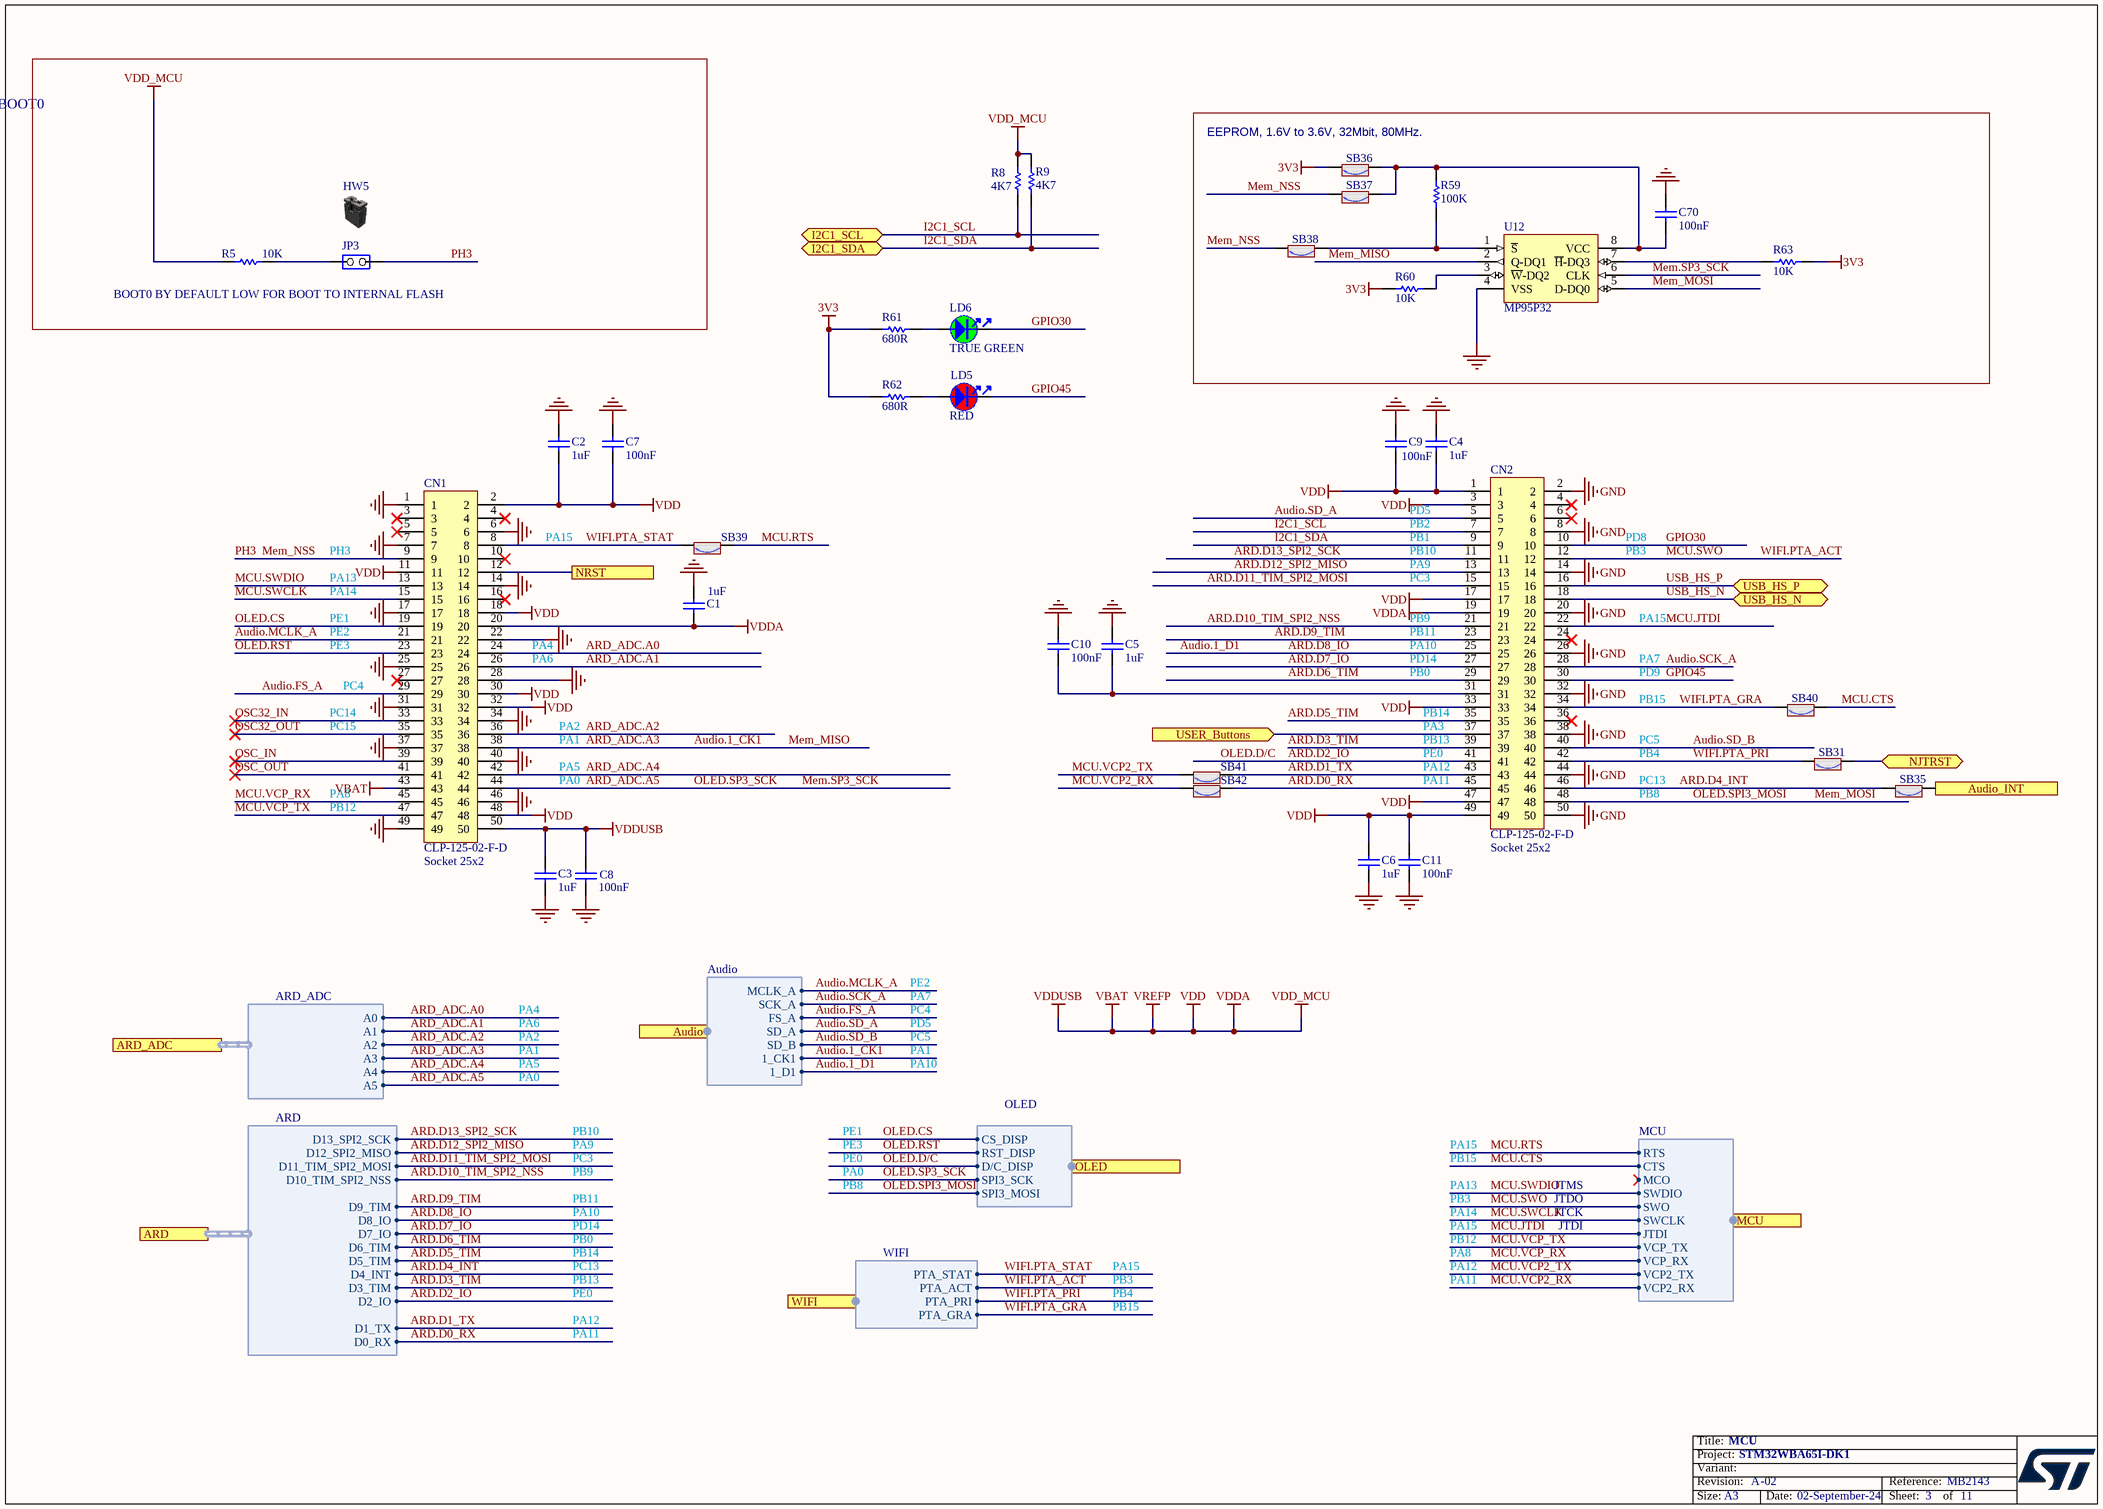
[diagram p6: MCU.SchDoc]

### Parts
C1  value 1uF  [C0805_H0P85]  (hidden comment: Capacitor)
C2  value 1uF  [C0805_H0P85]  (hidden comment: Capacitor)
C3  value 1uF  [C0805_H0P85]  (hidden comment: Capacitor)
C4  value 1uF  [C0805_H0P85]  (hidden comment: Capacitor)
C5  value 1uF  [C0805_H0P85]  (hidden comment: Capacitor)
C6  value 1uF  [C0805_H0P85]  (hidden comment: Capacitor)
C7  value 100nF  [C0402]  (hidden comment: Capacitor)
C8  value 100nF  [C0402]  (hidden comment: Capacitor)
C9  value 100nF  [C0402]  (hidden comment: Capacitor)
C10  value 100nF  [C0402]  (hidden comment: Capacitor)
C11  value 100nF  [C0402]  (hidden comment: Capacitor)
C70  value 100nF  [C0402]  (hidden comment: Capacitor)
CN1  CLP-125-02-F-D  value Socket 25x2  [CON_SAMTEC_CLP-125-02-F-D]
CN2  CLP-125-02-F-D  value Socket 25x2  [CON_SAMTEC_CLP-125-02-F-D]
HW5  Shunt Black 2.54mm  (value not drawn)  (mechanical)
JP3  Jumper_Header 2x1  [CON_SAMTEC_TSW-102-07-G-S]  (value not drawn)
LD5  value RED  [LED_0603_VISHAY_VLMS1300-GS08_RED_1A2K_H0P8]  (hidden comment: LED_red)
LD6  value TRUE GREEN  [LED_0603_VISHAY_VLMTG1300-GS08_GREEN_1A2K_H0P8]  (hidden comment: LED_green)
R5  value 10K  [R0603]
R8  value 4K7  [R0402]  (hidden comment: Resistor)
R9  value 4K7  [R0402]  (hidden comment: Resistor)
R59  value 100K  [R0402]  (hidden comment: Resistor)
R60  value 10K  [R0402]  (hidden comment: Resistor)
R61  value 680R  [R0402]  (hidden comment: Resistor)
R62  value 680R  [R0402]  (hidden comment: Resistor)
R63  value 10K  [R0402]  (hidden comment: Resistor)
SB31  (no value)  [SOLDER-BRIDGE_R0603-0R]
SB35  (no value)  [SOLDER-BRIDGE_R0603-0R]
SB36  (no value)  [SOLDER-BRIDGE_R0603-0R]
SB37  (no value)  [SOLDER-BRIDGE_R0603-0R]
SB38  (no value)  [SOLDER-BRIDGE_R0603-0R]
SB39  (no value)  [SOLDER-BRIDGE_R0603-0R]
SB40  (no value)  [SOLDER-BRIDGE_R0603-0R]
SB41  (no value)  [SOLDER-BRIDGE_R0603-0R]
SB42  (no value)  [SOLDER-BRIDGE_R0603-0R]
U12  value MP95P32  [ICC_SO8_5X4_P127]  (hidden comment: M95P32)

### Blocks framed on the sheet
PH3_BOOT0: HW5 JP3 R5
EEPROM, 1.6V to 3.6V, 32Mbit, 80MHz.: C70 R59 R60 R63 SB36-SB38 U12

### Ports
ARD (harness ARD), ARD_ADC (harness ARD_ADC), Audio (harness Audio), Audio_INT (in), I2C1_SCL (bidir), I2C1_SDA (bidir), MCU (harness MCU), NJTRST (bidir), NRST, OLED (harness OLED), USB_HS_N (bidir), USB_HS_P (bidir), USER_Buttons (in), WIFI (harness WIFI)

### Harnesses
ARD: D0_RX, D1_TX, D2_IO, D3_TIM, D4_INT, D5_TIM, D6_TIM, D7_IO, D8_IO, D9_TIM, D10_TIM_SPI2_NSS, D11_TIM_SPI2_MOSI, D12_SPI2_MISO, D13_SPI2_SCK
ARD_ADC: A0, A1, A2, A3, A4, A5
OLED: CS_DISP, RST_DISP, D/C_DISP, SPI3_SCK, SPI3_MOSI
Audio: MCLK_A, 1_CK1, FS_A, SD_A, SCK_A, SD_B, 1_D1
WIFI: PTA_STAT, PTA_ACT, PTA_PRI, PTA_GRA
MCU: MCO, SWDIO, SWO, VCP_TX, SWCLK, VCP_RX, JTDI, CTS, RTS, VCP2_RX, VCP2_TX

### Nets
3V3: R60.2 R61.1 R62.1 R63.1 SB36.2
GND: C1.2 C2.1 C3.1 C4.1 C5.1 C6.1 C7.1 C8.2 C9.1 C10.1 C11.1 C70.1 CN1.1 CN1.6 CN1.7 CN1.14 CN1.17 CN1.22 CN1.25 CN1.28 CN1.31 CN1.34 CN1.37 CN1.40 CN1.46 CN1.49 CN2.2 CN2.8 CN2.14 CN2.20 CN2.26 CN2.32 CN2.38 CN2.44 CN2.50 U12.4(VSS)
VBAT: C1.1 C2.2 C3.2 C4.2 C6.2 C7.2 C8.1 C9.2 C11.2 CN1.2 CN1.11 CN1.18 CN1.20 CN1.30 CN1.32 CN1.43 CN1.48 CN1.50 CN2.1 CN2.3 CN2.17 CN2.19 CN2.33 CN2.47 CN2.49 R5.1 R8.2 R9.2  [also labelled VDD, VDD_MCU, VDDA, VDDUSB, VREFP]
ARD.D0_RX: CN2.45 SB42.1 ; port ARD.D0_RX
ARD.D1_TX: CN2.43 SB41.1 ; port ARD.D1_TX
ARD.D2_IO: CN2.41 ; port ARD.D2_IO, port OLED.D/C_DISP  [also labelled OLED.D/C]
ARD.D3_TIM: CN2.39 ; port ARD.D3_TIM
ARD.D4_INT: CN2.46 SB35.2 ; port ARD.D4_INT
ARD.D5_TIM: CN2.35 ; port ARD.D5_TIM
ARD.D6_TIM: CN2.29 ; port ARD.D6_TIM
ARD.D7_IO: CN2.27 ; port ARD.D7_IO
ARD.D8_IO: CN2.25 ; port ARD.D8_IO, port Audio.1_D1  [also labelled Audio.1_D1]
ARD.D9_TIM: CN2.23 ; port ARD.D9_TIM
ARD.D10_TIM_SPI2_NSS: CN2.21 ; port ARD.D10_TIM_SPI2_NSS
ARD.D11_TIM_SPI2_MOSI: CN2.15 ; port ARD.D11_TIM_SPI2_MOSI
ARD.D12_SPI2_MISO: CN2.13 ; port ARD.D12_SPI2_MISO
ARD.D13_SPI2_SCK: CN2.11 ; port ARD.D13_SPI2_SCK
ARD_ADC.A0: CN1.24 ; port ARD_ADC.A0
ARD_ADC.A1: CN1.26 ; port ARD_ADC.A1
ARD_ADC.A2: CN1.36 ; port ARD_ADC.A2
ARD_ADC.A3: CN1.38 U12.2(Q-DQ1) ; port ARD_ADC.A3, port Audio.1_CK1  [also labelled Audio.1_CK1, Mem_MISO]
ARD_ADC.A4: CN1.42 ; port ARD_ADC.A4
ARD_ADC.A5: CN1.44 U12.6(CLK) ; port ARD_ADC.A5, port OLED.SPI3_SCK  [also labelled Mem.SP3_SCK, OLED.SP3_SCK]
Audio.FS_A: CN1.29 ; port Audio.FS_A
Audio.MCLK_A: CN1.21 ; port Audio.MCLK_A
Audio.SCK_A: CN2.28 ; port Audio.SCK_A
Audio.SD_A: CN2.5 ; port Audio.SD_A
Audio.SD_B: CN2.40 ; port Audio.SD_B
GPIO30: CN2.10 LD6.2
GPIO45: CN2.30 LD5.2
I2C1_SCL: CN2.7 R8.1 ; port I2C1_SCL
I2C1_SDA: CN2.9 R9.1 ; port I2C1_SDA
JNTRST: SB31.1 ; port NJTRST
MCU.CTS: SB40.1 ; port MCU.CTS
MCU.JTDI: CN2.22 ; port MCU.JTDI
MCU.RTS: SB39.1 ; port MCU.RTS
MCU.SWCLK: CN1.15 ; port MCU.SWCLK
MCU.SWDIO: CN1.13 ; port MCU.SWDIO
MCU.SWO: CN2.12 ; port WIFI.PTA_ACT, port MCU.SWO  [also labelled WIFI.PTA_ACT]
MCU.VCP2_RX: SB42.2 ; port MCU.VCP2_RX
MCU.VCP2_TX: SB41.2 ; port MCU.VCP2_TX
MCU.VCP_RX: CN1.45 ; port MCU.VCP_RX
MCU.VCP_TX: CN1.47 ; port MCU.VCP_TX
Mem_MOSI: CN2.48 U12.5(D-DQ0) ; port OLED.SPI3_MOSI  [also labelled OLED.SPI3_MOSI]
Mem_NSS: CN1.9 JP3.1(COMMON) SB37.2 SB38.2  [also labelled PH3]
NRST: CN1.12 ; port NRST
OLED.CS: CN1.19 ; port OLED.CS_DISP
OLED.RST: CN1.23 ; port OLED.RST_DISP
OSC32_IN: CN1.33
OSC32_OUT: CN1.35
OSC_IN: CN1.39
OSC_OUT: CN1.41
USB_HS_N: CN2.18 ; port USB_HS_N
USB_HS_P: CN2.16 ; port USB_HS_P
WIFI.PTA_GRA: CN2.34 SB40.2 ; port WIFI.PTA_GRA
WIFI.PTA_PRI: CN2.42 SB31.2 ; port WIFI.PTA_PRI
WIFI.PTA_STAT: CN1.8 SB39.2 ; port WIFI.PTA_STAT
NetB1_2: CN2.37 ; port USER_Buttons
NetC5_2: C5.2 C10.2 CN2.31
NetC70_2: C70.2 R59.1 SB36.1 SB37.1 U12.8(VCC)
NetJP3_2: JP3.2(NO) R5.2
NetLD5_1: LD5.1 R62.2
NetLD6_1: LD6.1 R61.2
NetR59_2: R59.2 SB38.1 U12.1(~{S})
NetR60_1: R60.1 U12.3(~{W}-DQ2)
NetR63_2: R63.2 U12.7(~{H}-DQ3)
NetSB32_2: SB35.1 ; port Audio_INT

Not connected (* = marked no-connect by the designer): CN1 3* 4* 5* 10* 16* 27*; CN2 4* 6* 24* 36*

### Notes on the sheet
- BOOT0 BY DEFAULT LOW FOR BOOT TO INTERNAL FLASH
- PD5
- PH3
- PA13
- PA15
- PB2
- PB1
- PB10
- PA9
- PC3
- PD8
- PB3
- PA14
- PE1
- PE2
- PE3
- PA4
- PB9
- PA10
- PB11
- PC14
- PC4
- PA6
- PD14
- PB0
- (near CN2) PB14
- PA7
- PD9
- PB15
- PC15
- PA1
- PA2
- PA5
- PA0
- (near CN2) PB13
- (near CN2) PE0
- (near CN2) PA12
- PA11
- (near CN2) PA3
- PC13
- PC5
- PB4
- PA8
- PB12
- PB8
- PE0
- JTMS
- PB14
- JTDO
- JTCK
- JTDI
- PB13
- PA12

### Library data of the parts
C1-C6 = MCD-01550: Capacitor, MLCC, 1uF, 16V, X5R, +/-10%, 0805, T=0.85mm; Part_Preference: Recommended; Manufacturer: YAGEO; Manufacturer_Part_Number: CC0805KRX5R7BB105; Component_Country_Of_Origin: China; ShowFields: YES; ID: 3650
C7-C11 = MCD-02355: as C44 on sheet STLink_V3EC
C70 = MCD-00006: Capacitor, MLCC, 100nF, 16V, X7R, +/-10%, 0402, T=0.5mm; Part_Preference: Recommended; Manufacturer: YAGEO; Manufacturer_Part_Number: CC0402KRX7R7BB104; Partial_Alternate_Internal_Part_Number: MCD-03299; Order_Code_RS: 9402047; Component_Country_Of_Origin: China; ShowFields: YES; ID: 2474
CN1 CN2 = MCD-02705: Socket, 25x2, 1.27mm, VR, SMD, T=2.29mm; Part_Type: Connector; Part_Preference: Recommended; Manufacturer: SAMTEC; Order_Code_RS: 180-3642; Component_Country_Of_Origin: USA; ShowFields: YES; ID: 4811
HW5 = MCD-00043: as HW4 on sheet Board_Power
JP3 = MCD-00045: as JP2 on sheet Board_Power
LD5 = MCD-00587: LED Red, 0603 SMD, 2V Forward Voltage; Part_Type: Display; Manufacturer_Part_Number: VLMS1300-GS08; Manufacturer: VISHAY; Part_Preference: Recommended; Alternate_Internal_Part_Number: MCD-02401; Component_Country_Of_Origin: China
LD6 = MCD-00589: LED Green, 0603 SMD, Fw Voltage = 2.8V - 3.6V; Part_Type: Display; Manufacturer_Part_Number: VLMTG1300-GS08; Manufacturer: VISHAY; Part_Preference: Recommended; Order_Code_RS: 7730452; Component_Country_Of_Origin: China
R5 = MCD-00220: Resistor,10K,0603,1%,1/10W; Manufacturer_Part_Number: RC0603FR-0710KL; Manufacturer: YAGEO; Provided_By: Subcon; Initial_Board_Reference: MB1319
R8 R9 = MCD-00065: Resistor,4K7,0402,1%,1/16W; Manufacturer_Part_Number: RC0402FR-074K7L; Manufacturer: YAGEO; Alternate_Manufacturer_Part_Number: RT0402FRE074K7L; Provided_By: SUBCO
R59 = MCD-00059: Resistor, 100K, 0402, +/-1%, 1/16W; Part_Preference: Recommended; Manufacturer: YAGEO; Manufacturer_Part_Number: RC0402FR-07100KL; Component_Country_Of_Origin: China
R60 R63 = MCD-00053: Resistor, 10K, 0402, +/-1%, 1/16W; BMS_Part_Number: 9131590; Part_Preference: Recommended; Manufacturer: YAGEO; Manufacturer_Part_Number: RC0402FR-0710KL
R61 R62 = MCD-00507: Resistor, 680R, 0402, +/-1%, 1/16W; Manufacturer_Part_Number: RC0402FR-07680RL; Manufacturer: YAGEO; Part_Preference: Recommended; Component_Country_Of_Origin: China
SB31 SB35-SB42 = MCD-00071: as SB13 on sheet Board_Power
U12 = MCD-03804: Memory, EEPROM, 1.6V to 3.6V, 32Mbit, 80MHz, SO8N, SPI interface; Part_Type: IC; Manufacturer_Part_Number: M95P32-IXMNT/E; Manufacturer: STMICROELECTRONICS; Part_Preference: Recommended; Provided_By: SUBCO; ECCN_US: EAR99; ECCN_EU: NEC; Component_Country_Of_Origin: China; ShowFields: YES; ID: 5920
